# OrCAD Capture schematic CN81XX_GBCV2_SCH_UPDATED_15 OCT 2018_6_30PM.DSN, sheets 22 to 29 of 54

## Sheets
22 23.USB2514BI-USB HUB: size A; title: USB2514BI-USB HUB
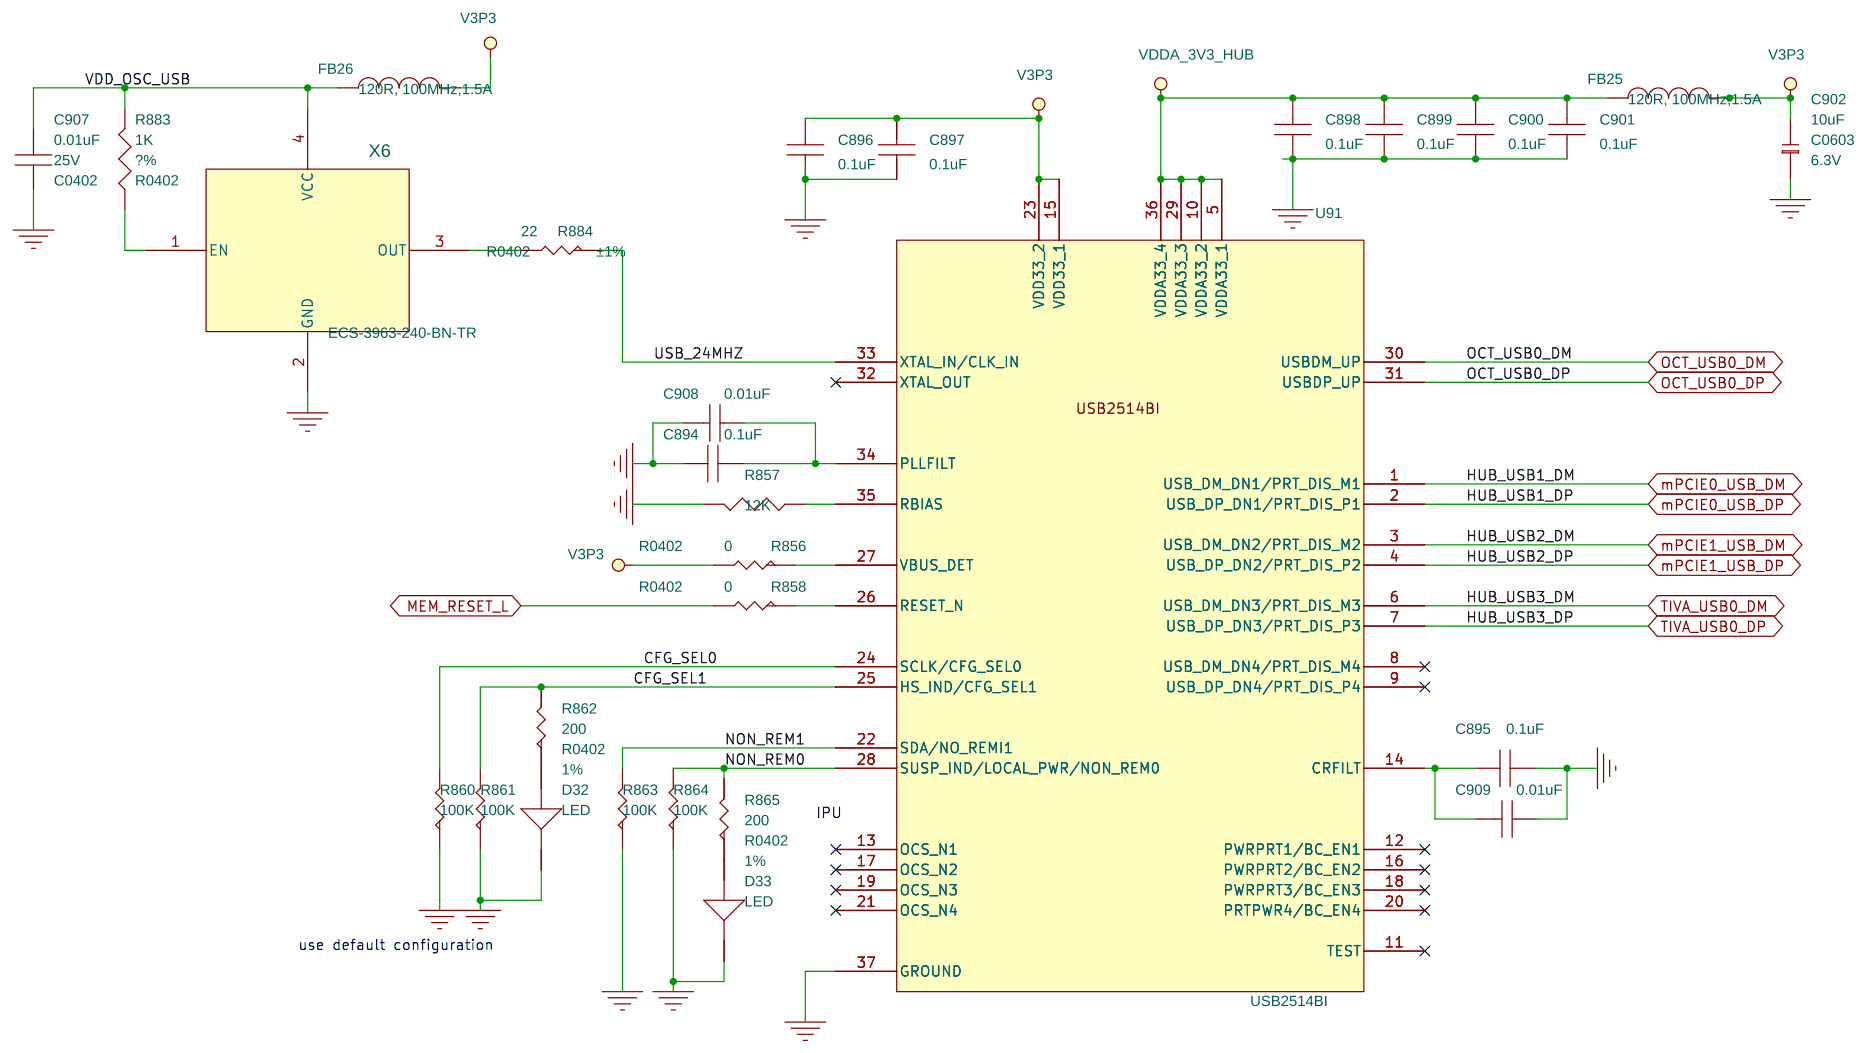
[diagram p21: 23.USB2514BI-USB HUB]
23 24.ETH PORT3 TO BB: size B; title: ETH PORT3 TO BB
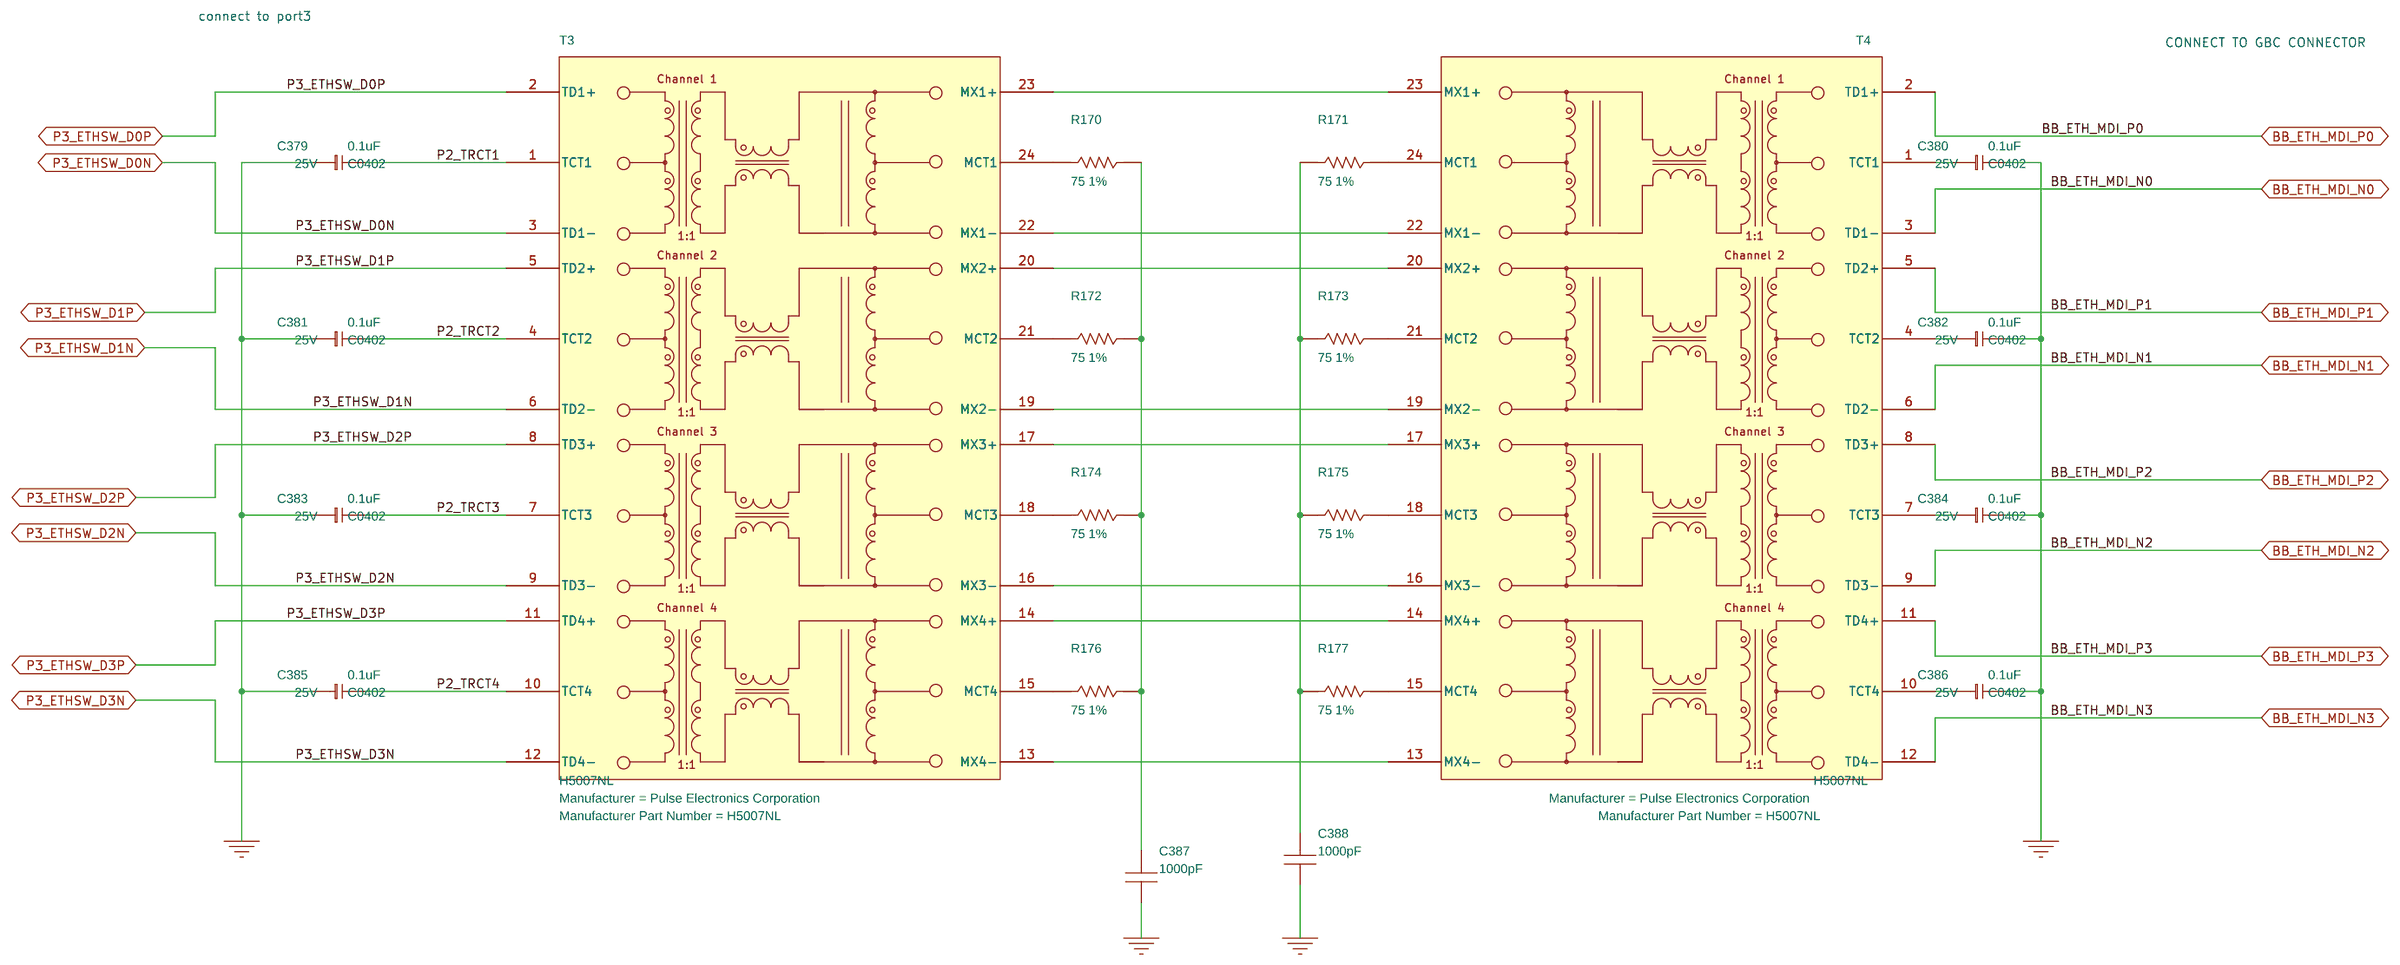
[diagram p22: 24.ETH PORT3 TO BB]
24 26.BOOT SPI FLASH & NAND: size B; title: BOOT SPI FLASH & NAND  FLASH
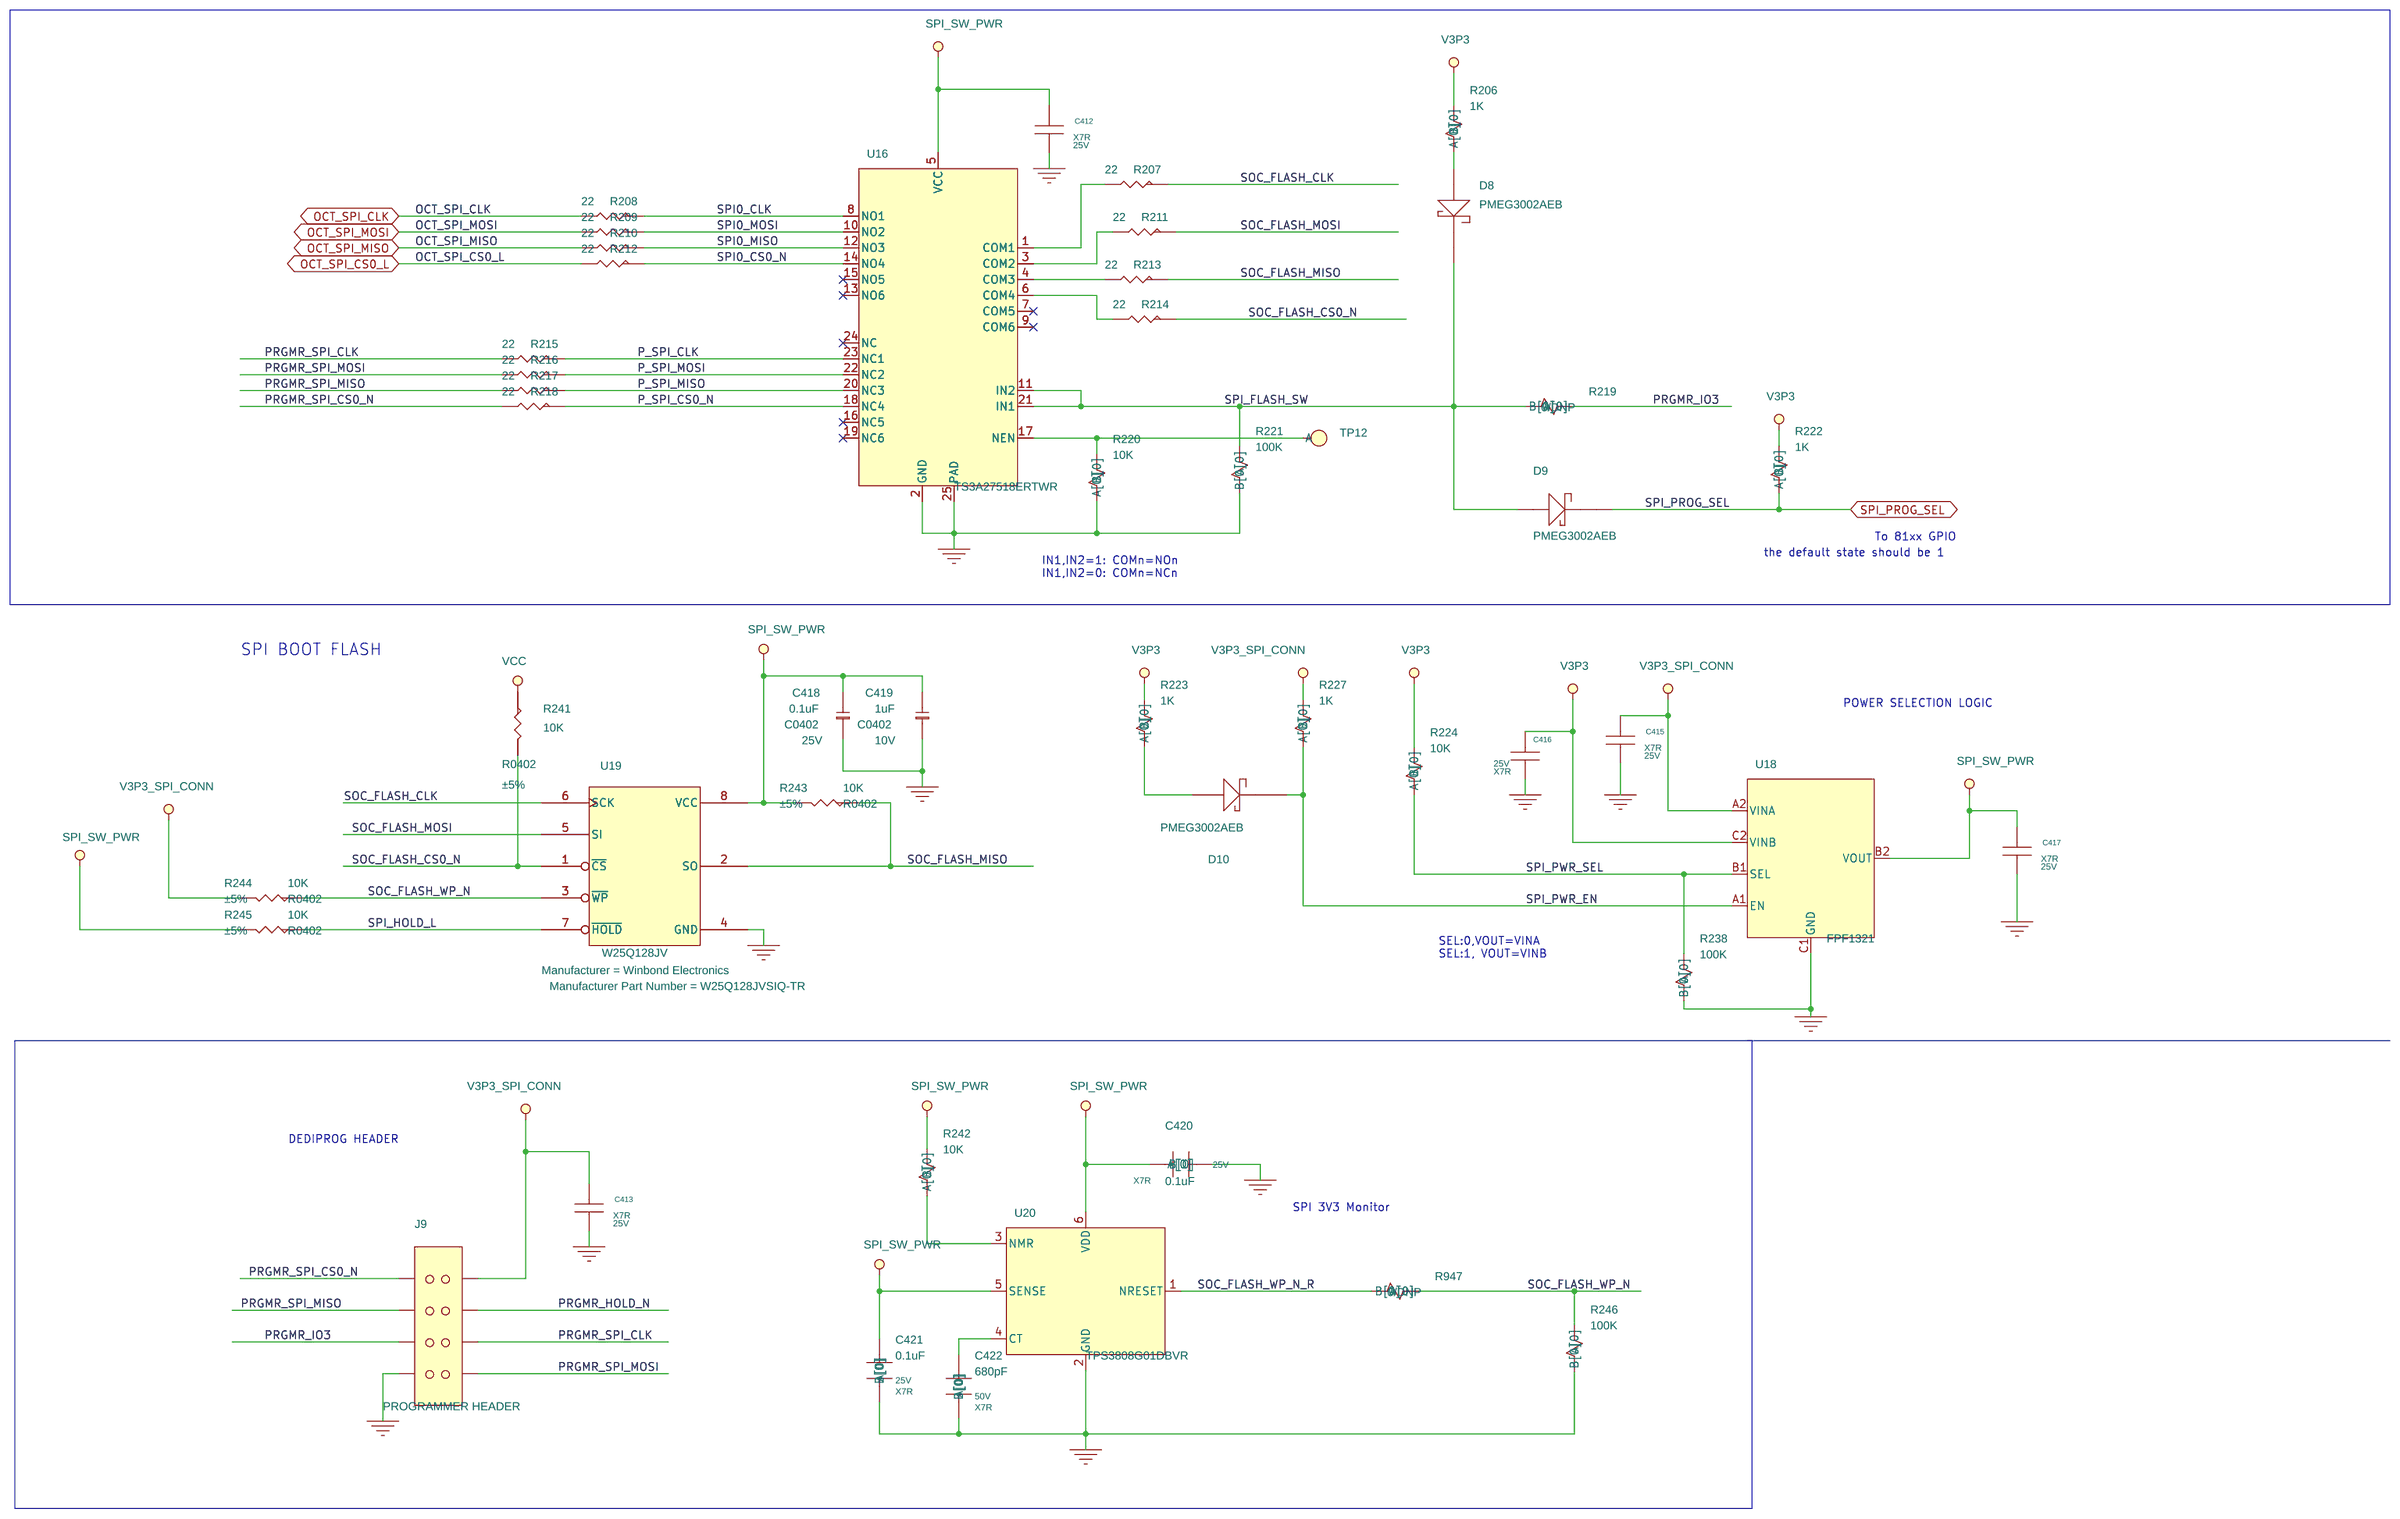
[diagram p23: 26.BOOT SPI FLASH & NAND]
25 27.OCT-UART0: size B; title: OCT-UART 0
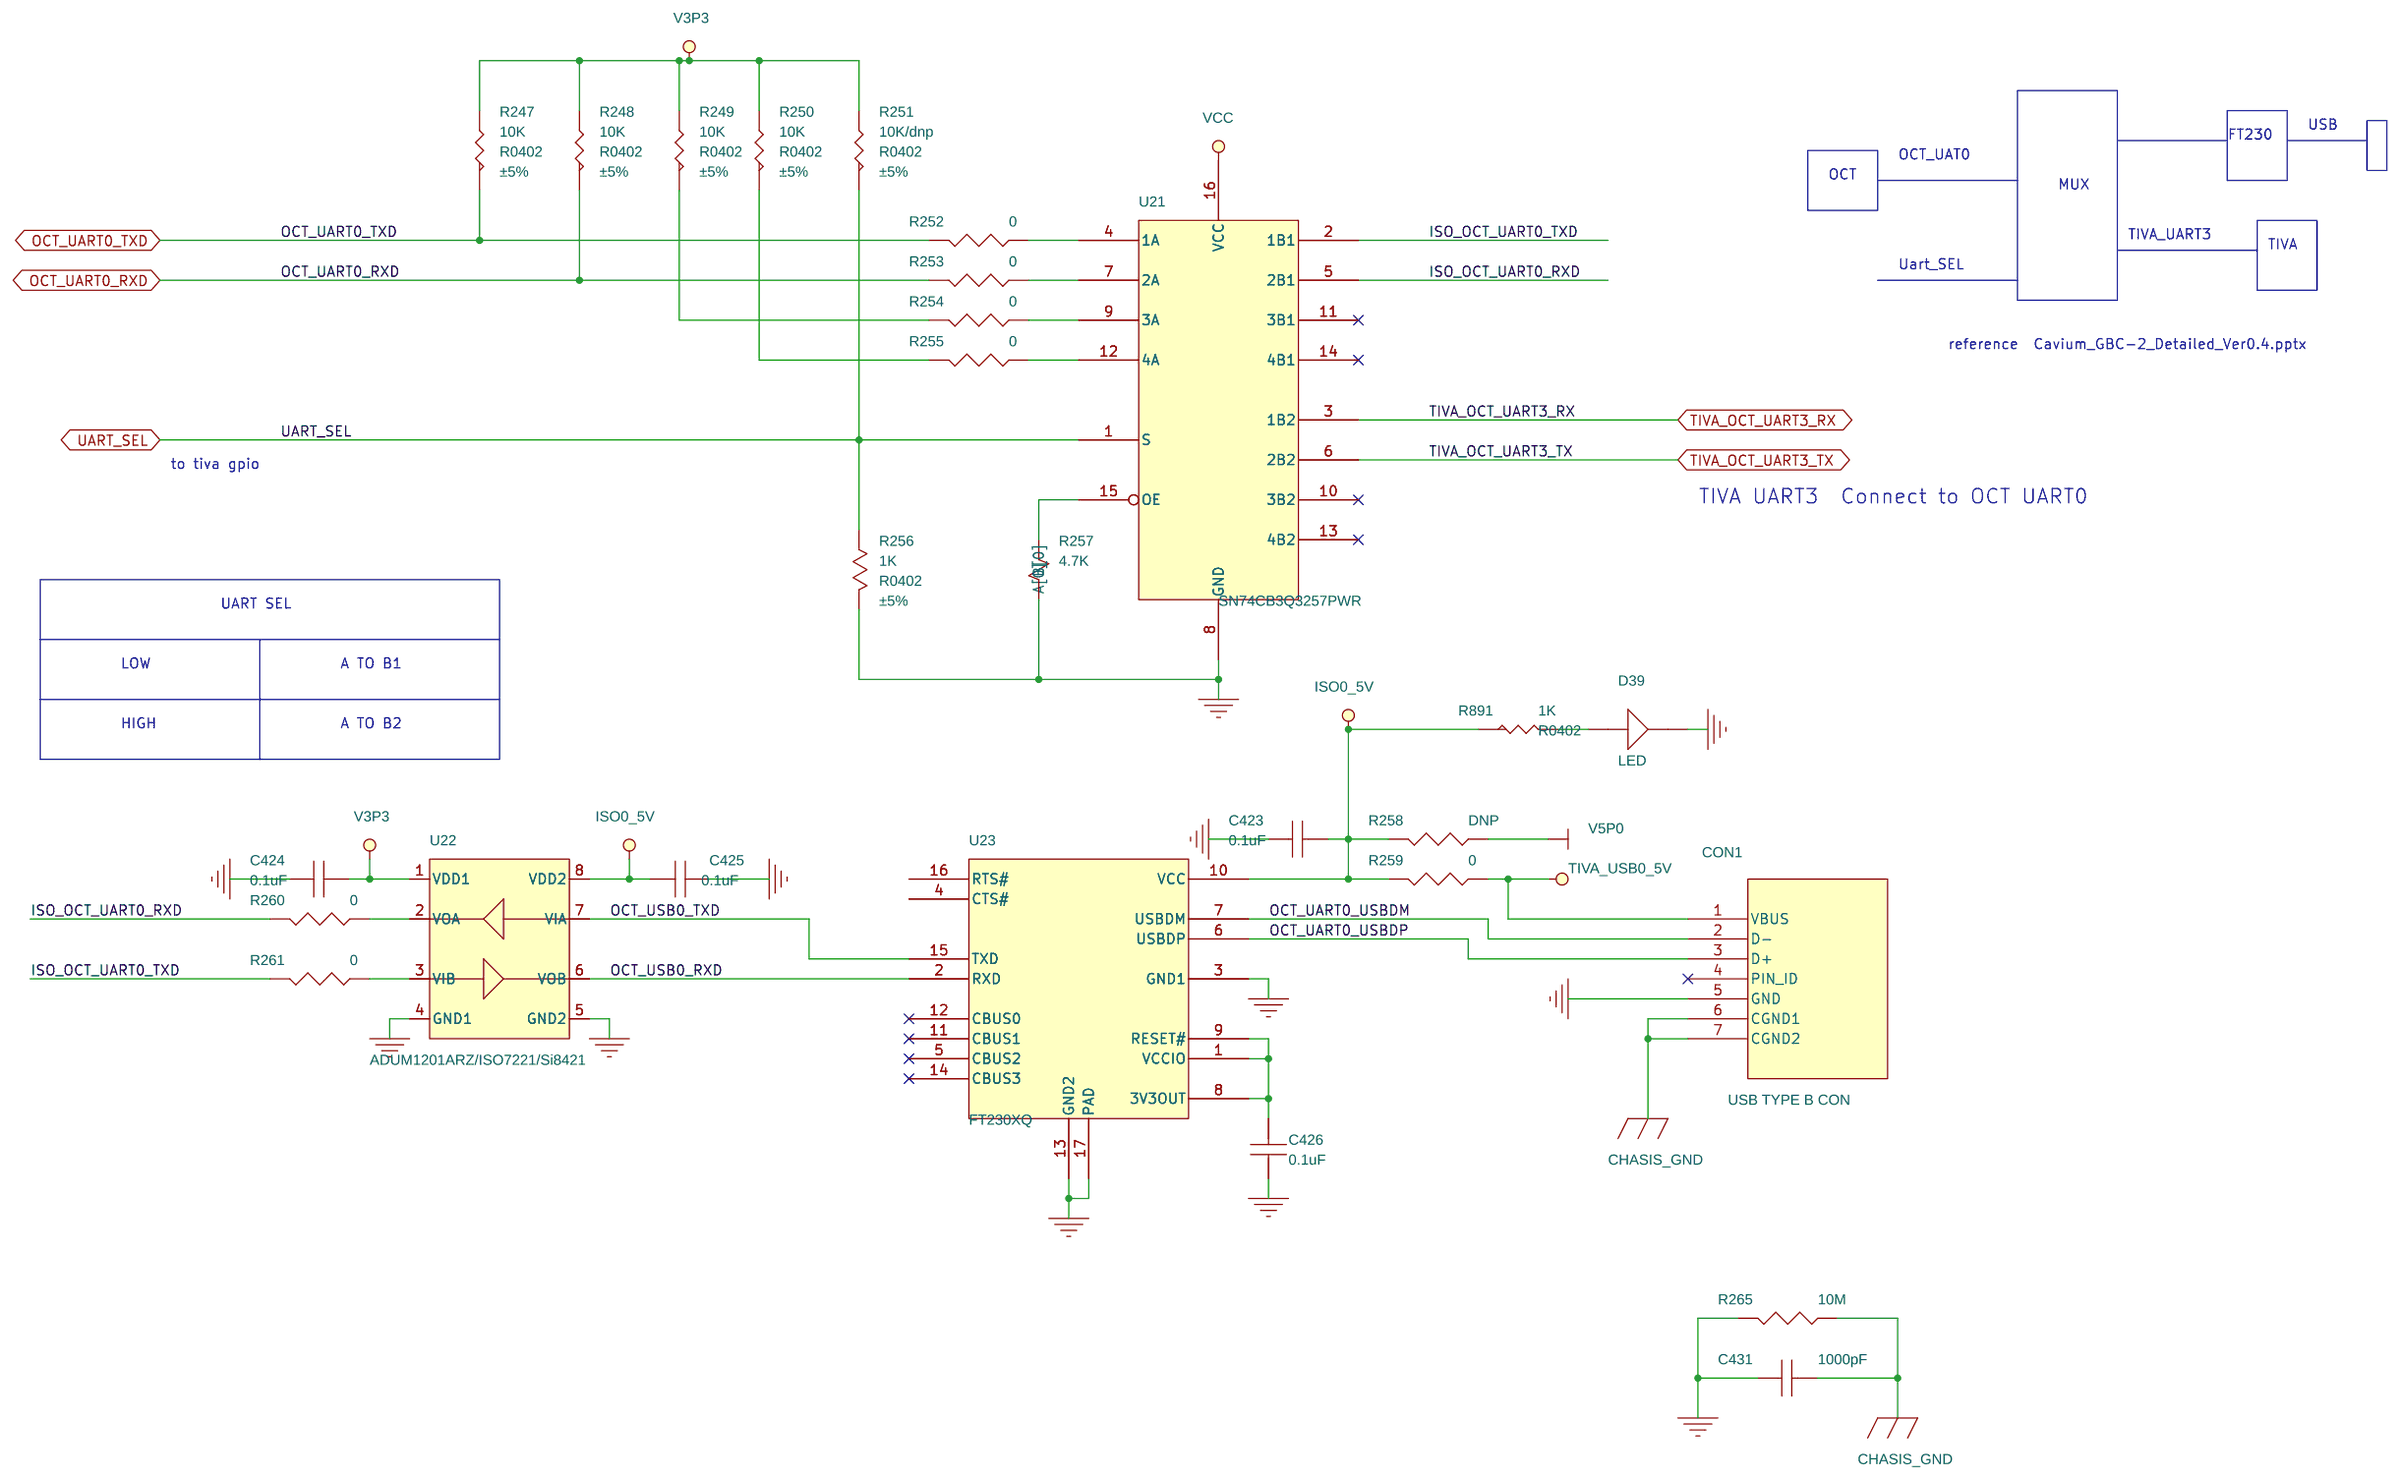
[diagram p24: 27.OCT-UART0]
26 28.DLM2_0 TO MINI PCIE0: size B; title: DLM2_0 TO MINI PCIE
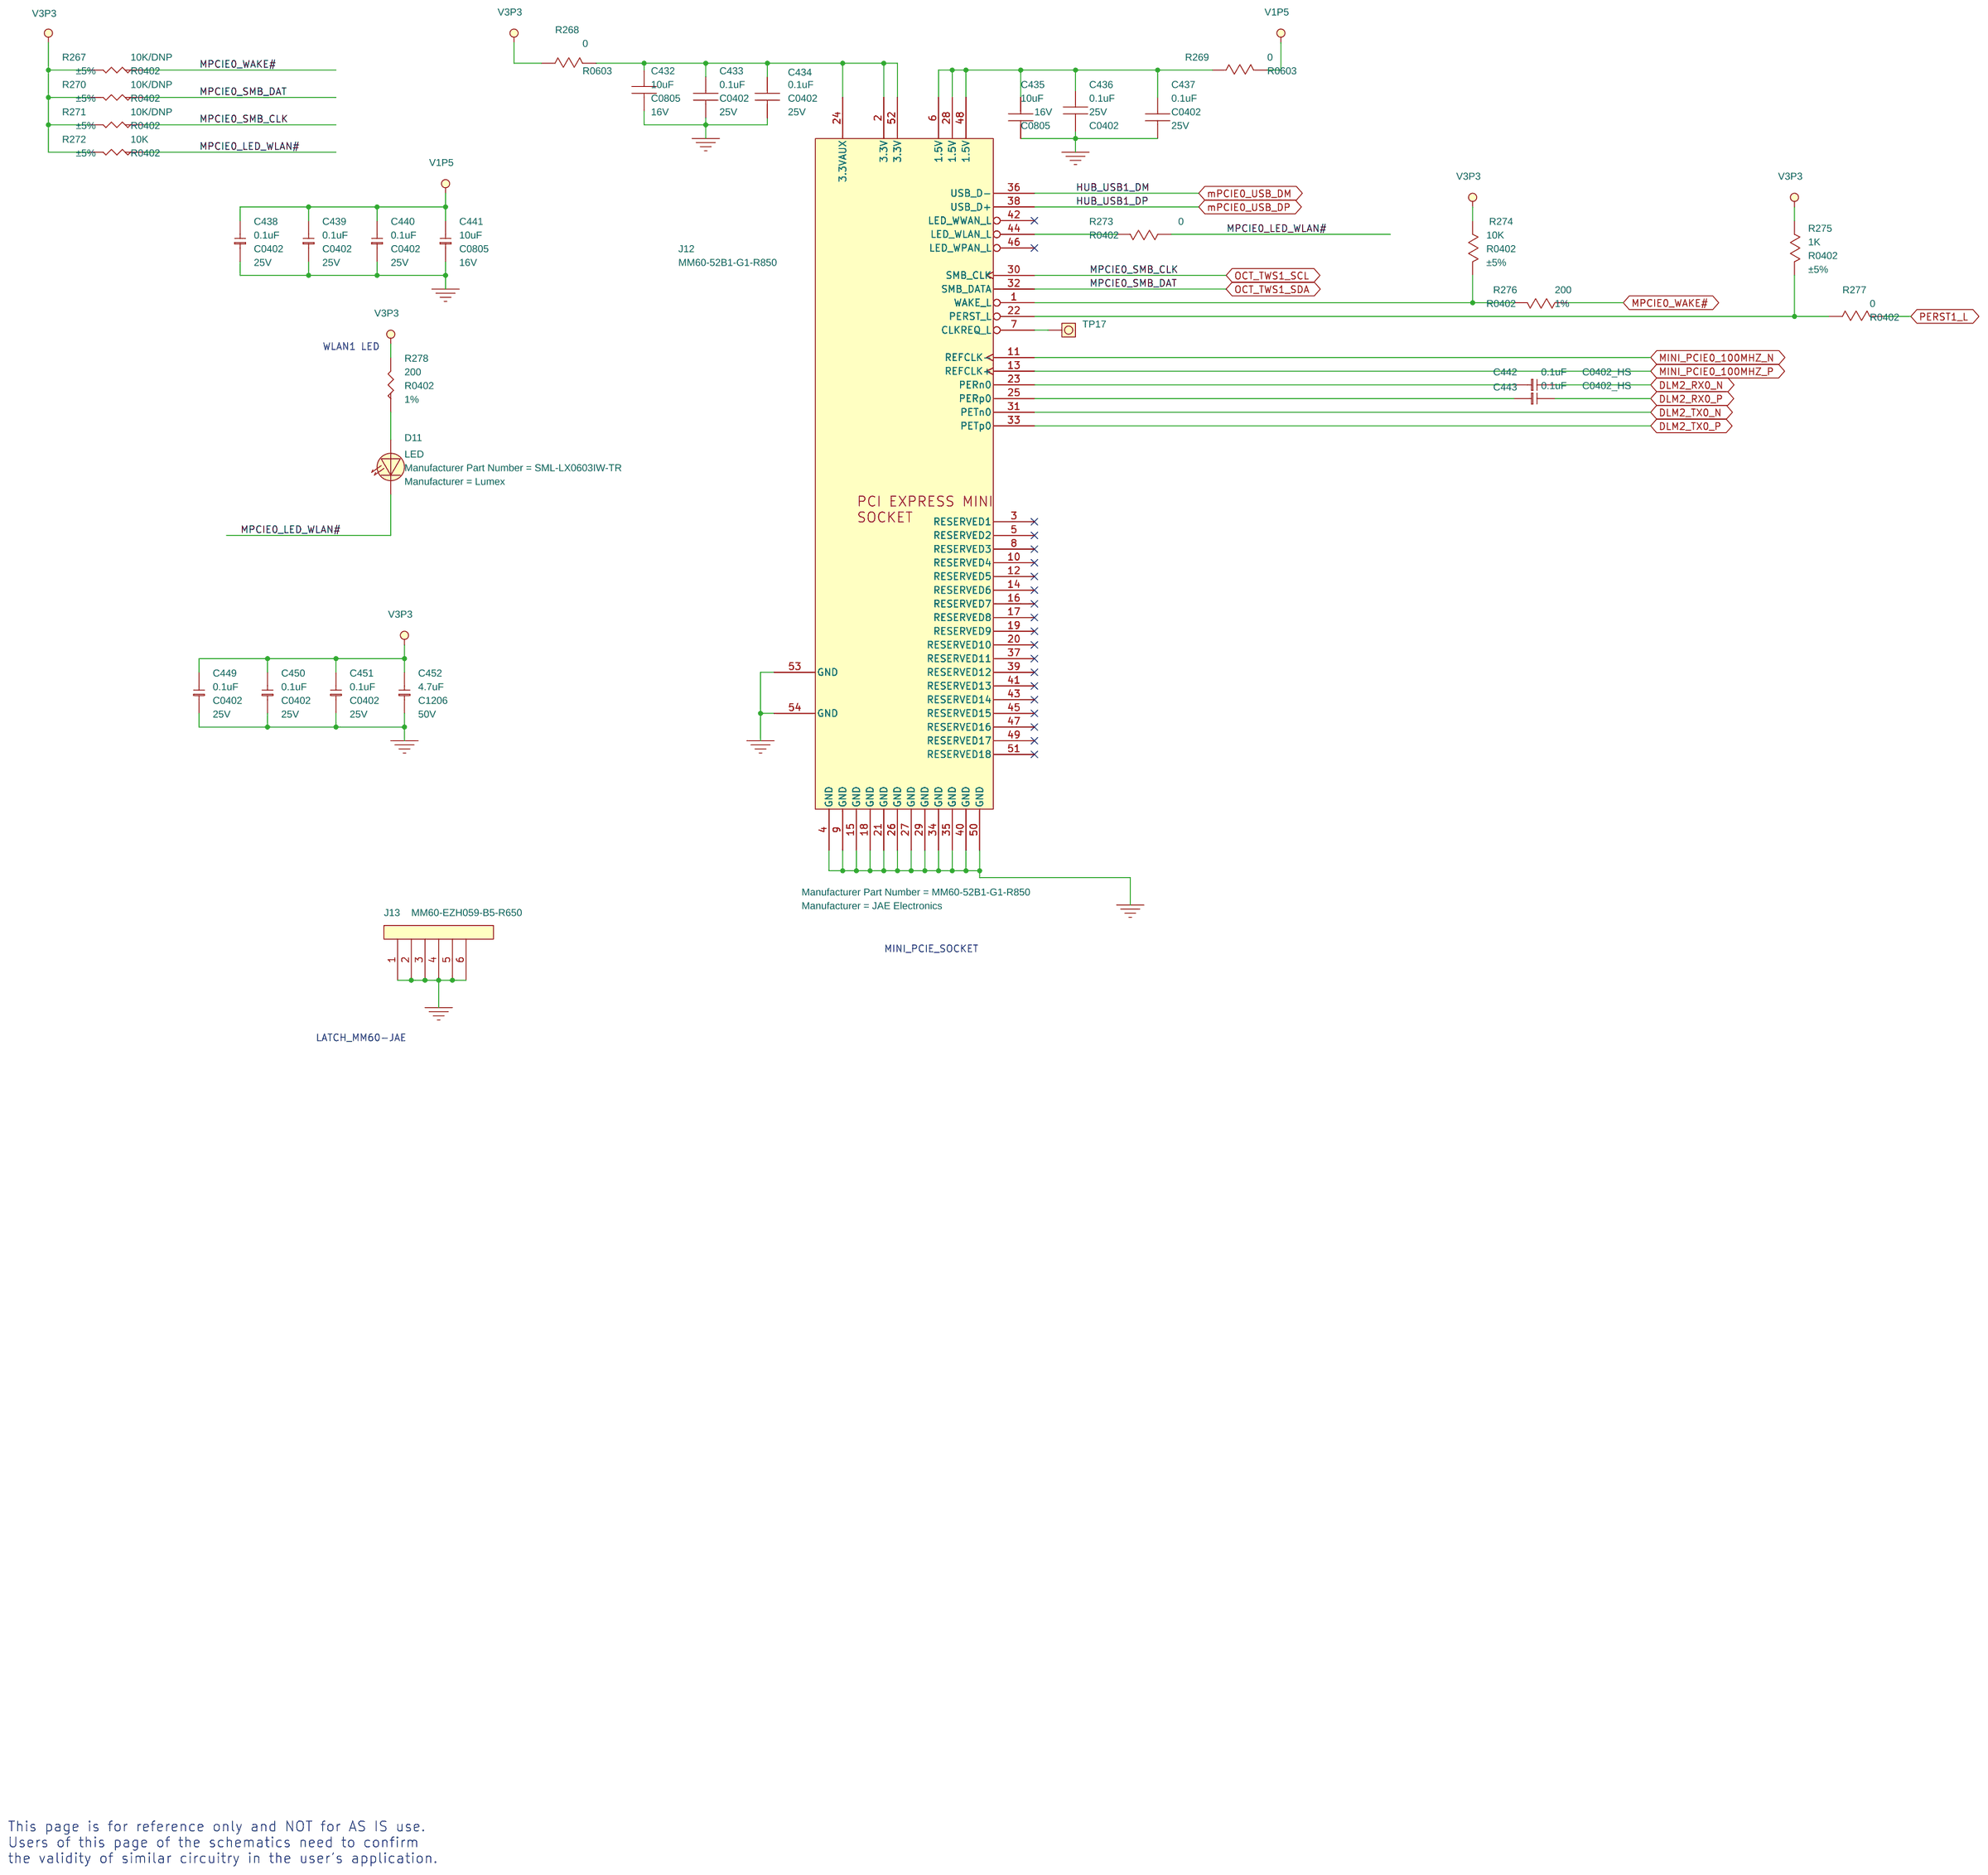
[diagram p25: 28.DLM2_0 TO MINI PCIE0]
27 29.DLM2_1 TO MINI PCIE1: size B; title: DLM2_1 TO MINI PCIE
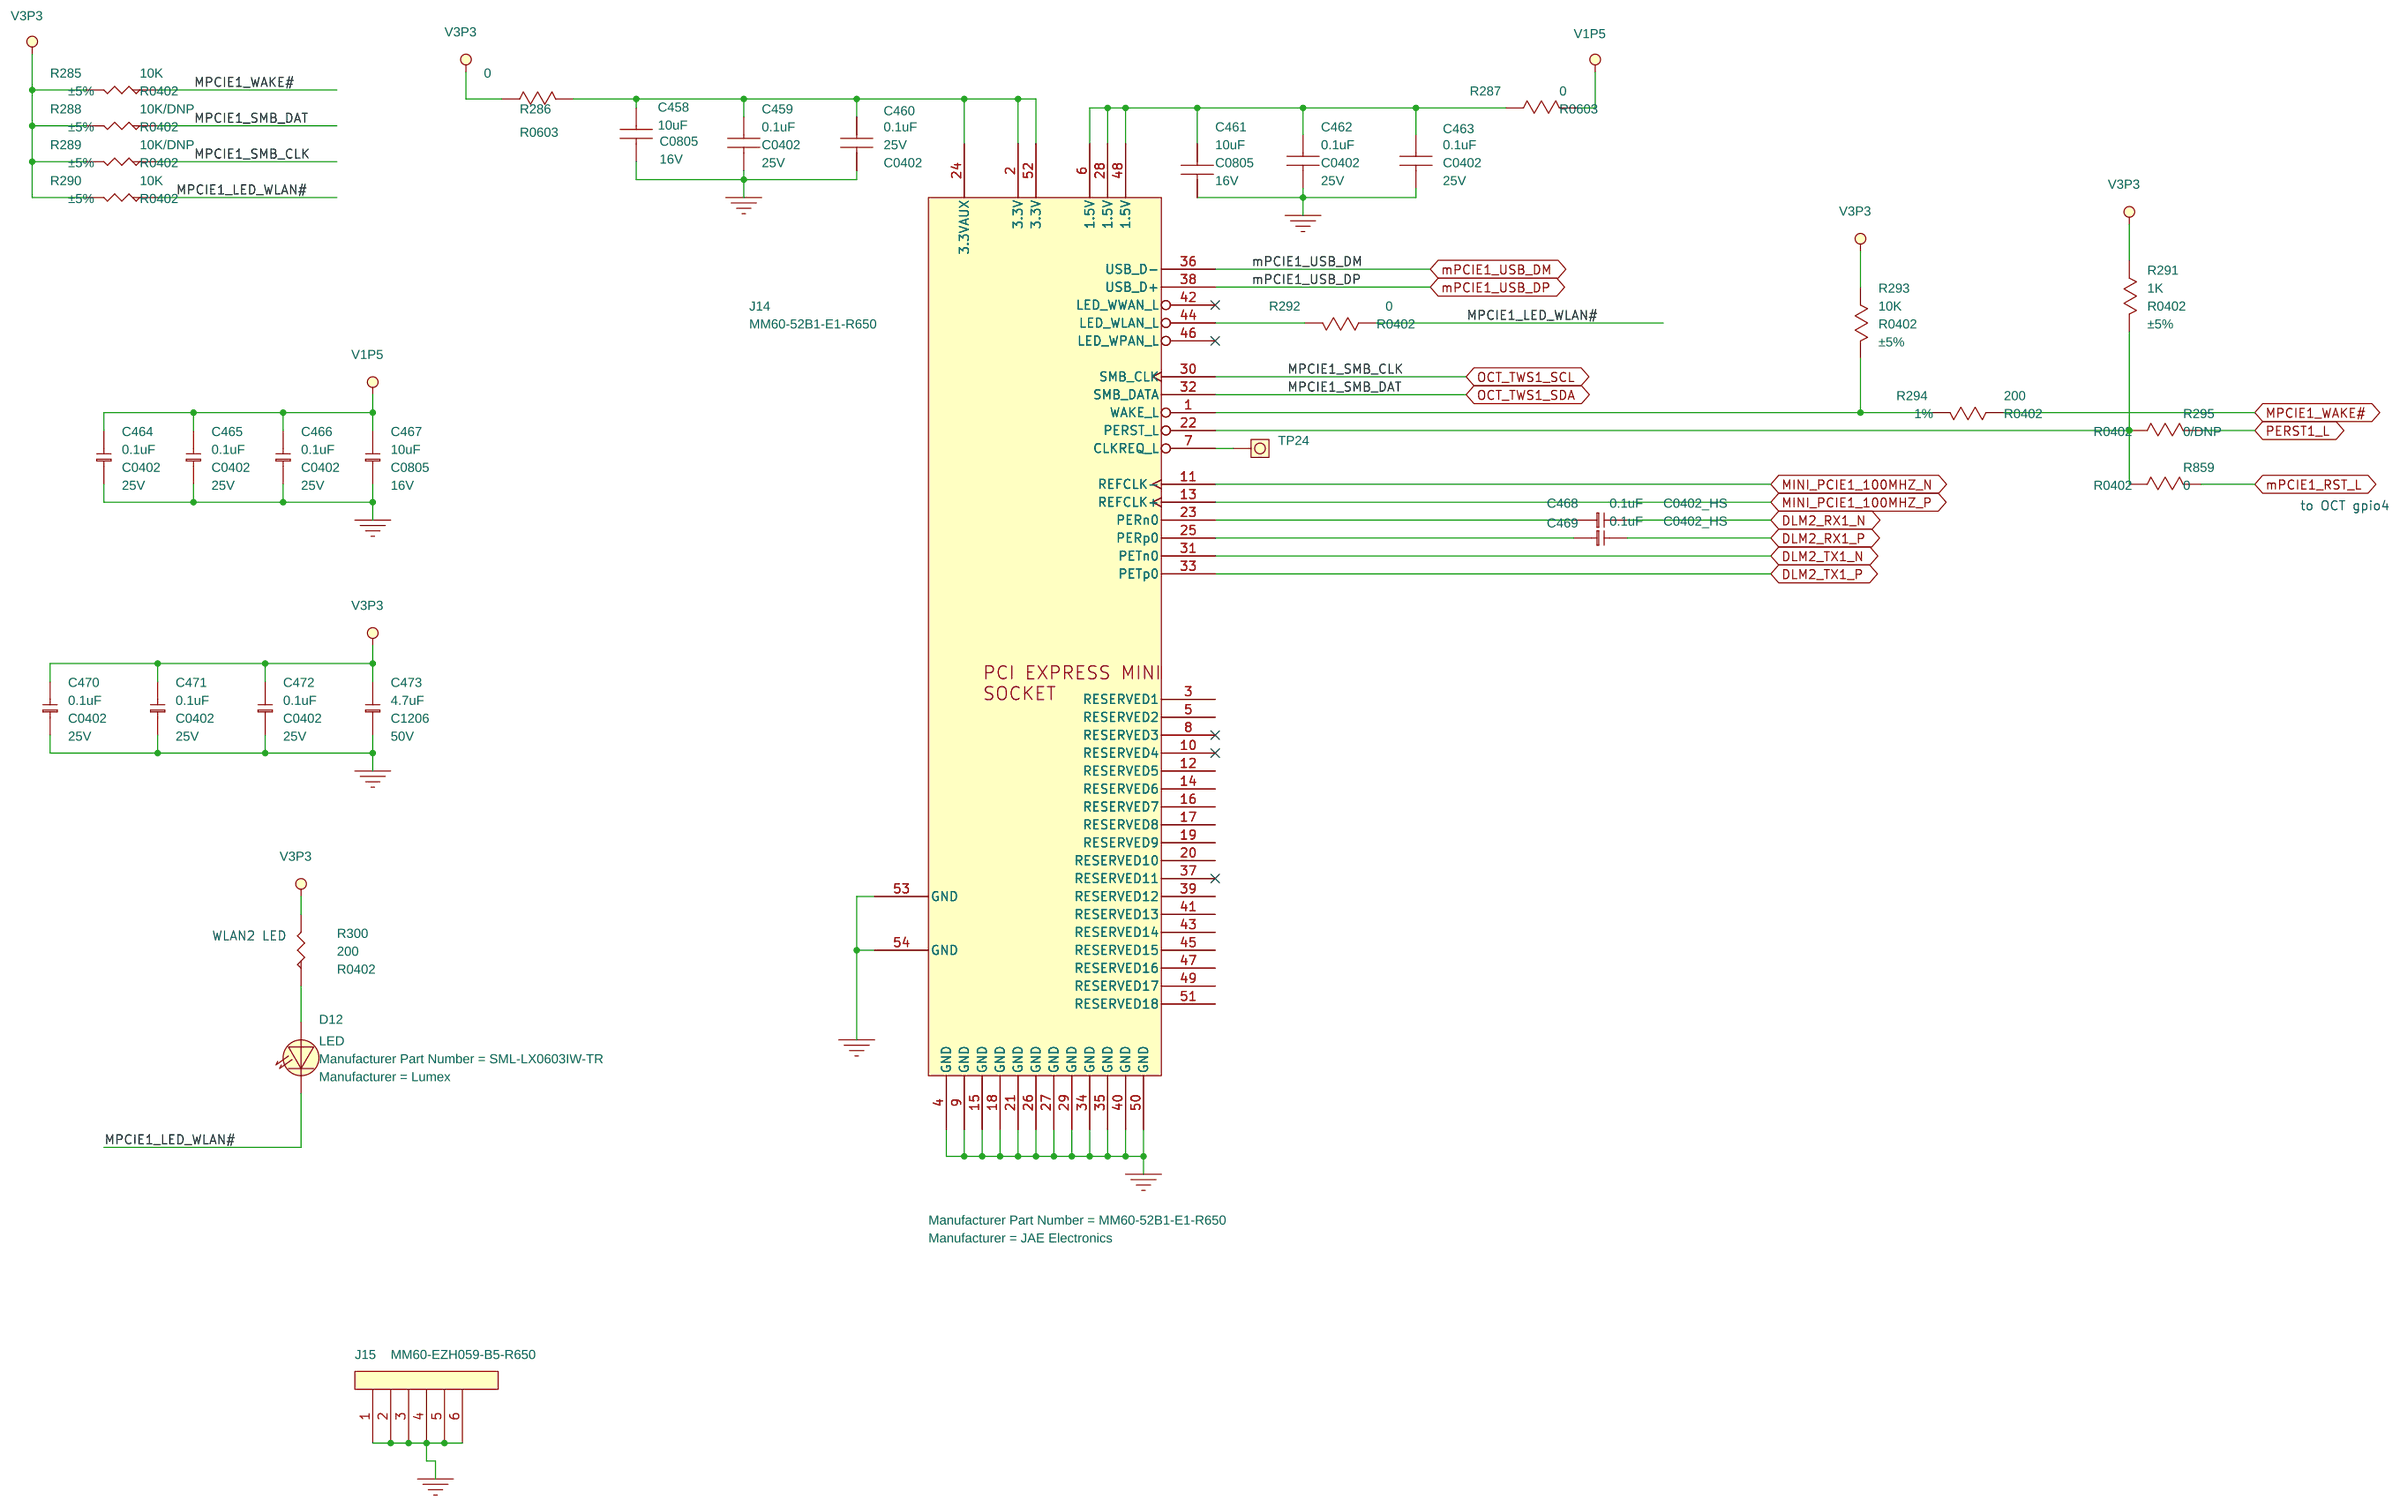
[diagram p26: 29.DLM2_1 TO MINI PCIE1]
28 30.POWER ENTRY: size Custom; title: POWER ENTRY
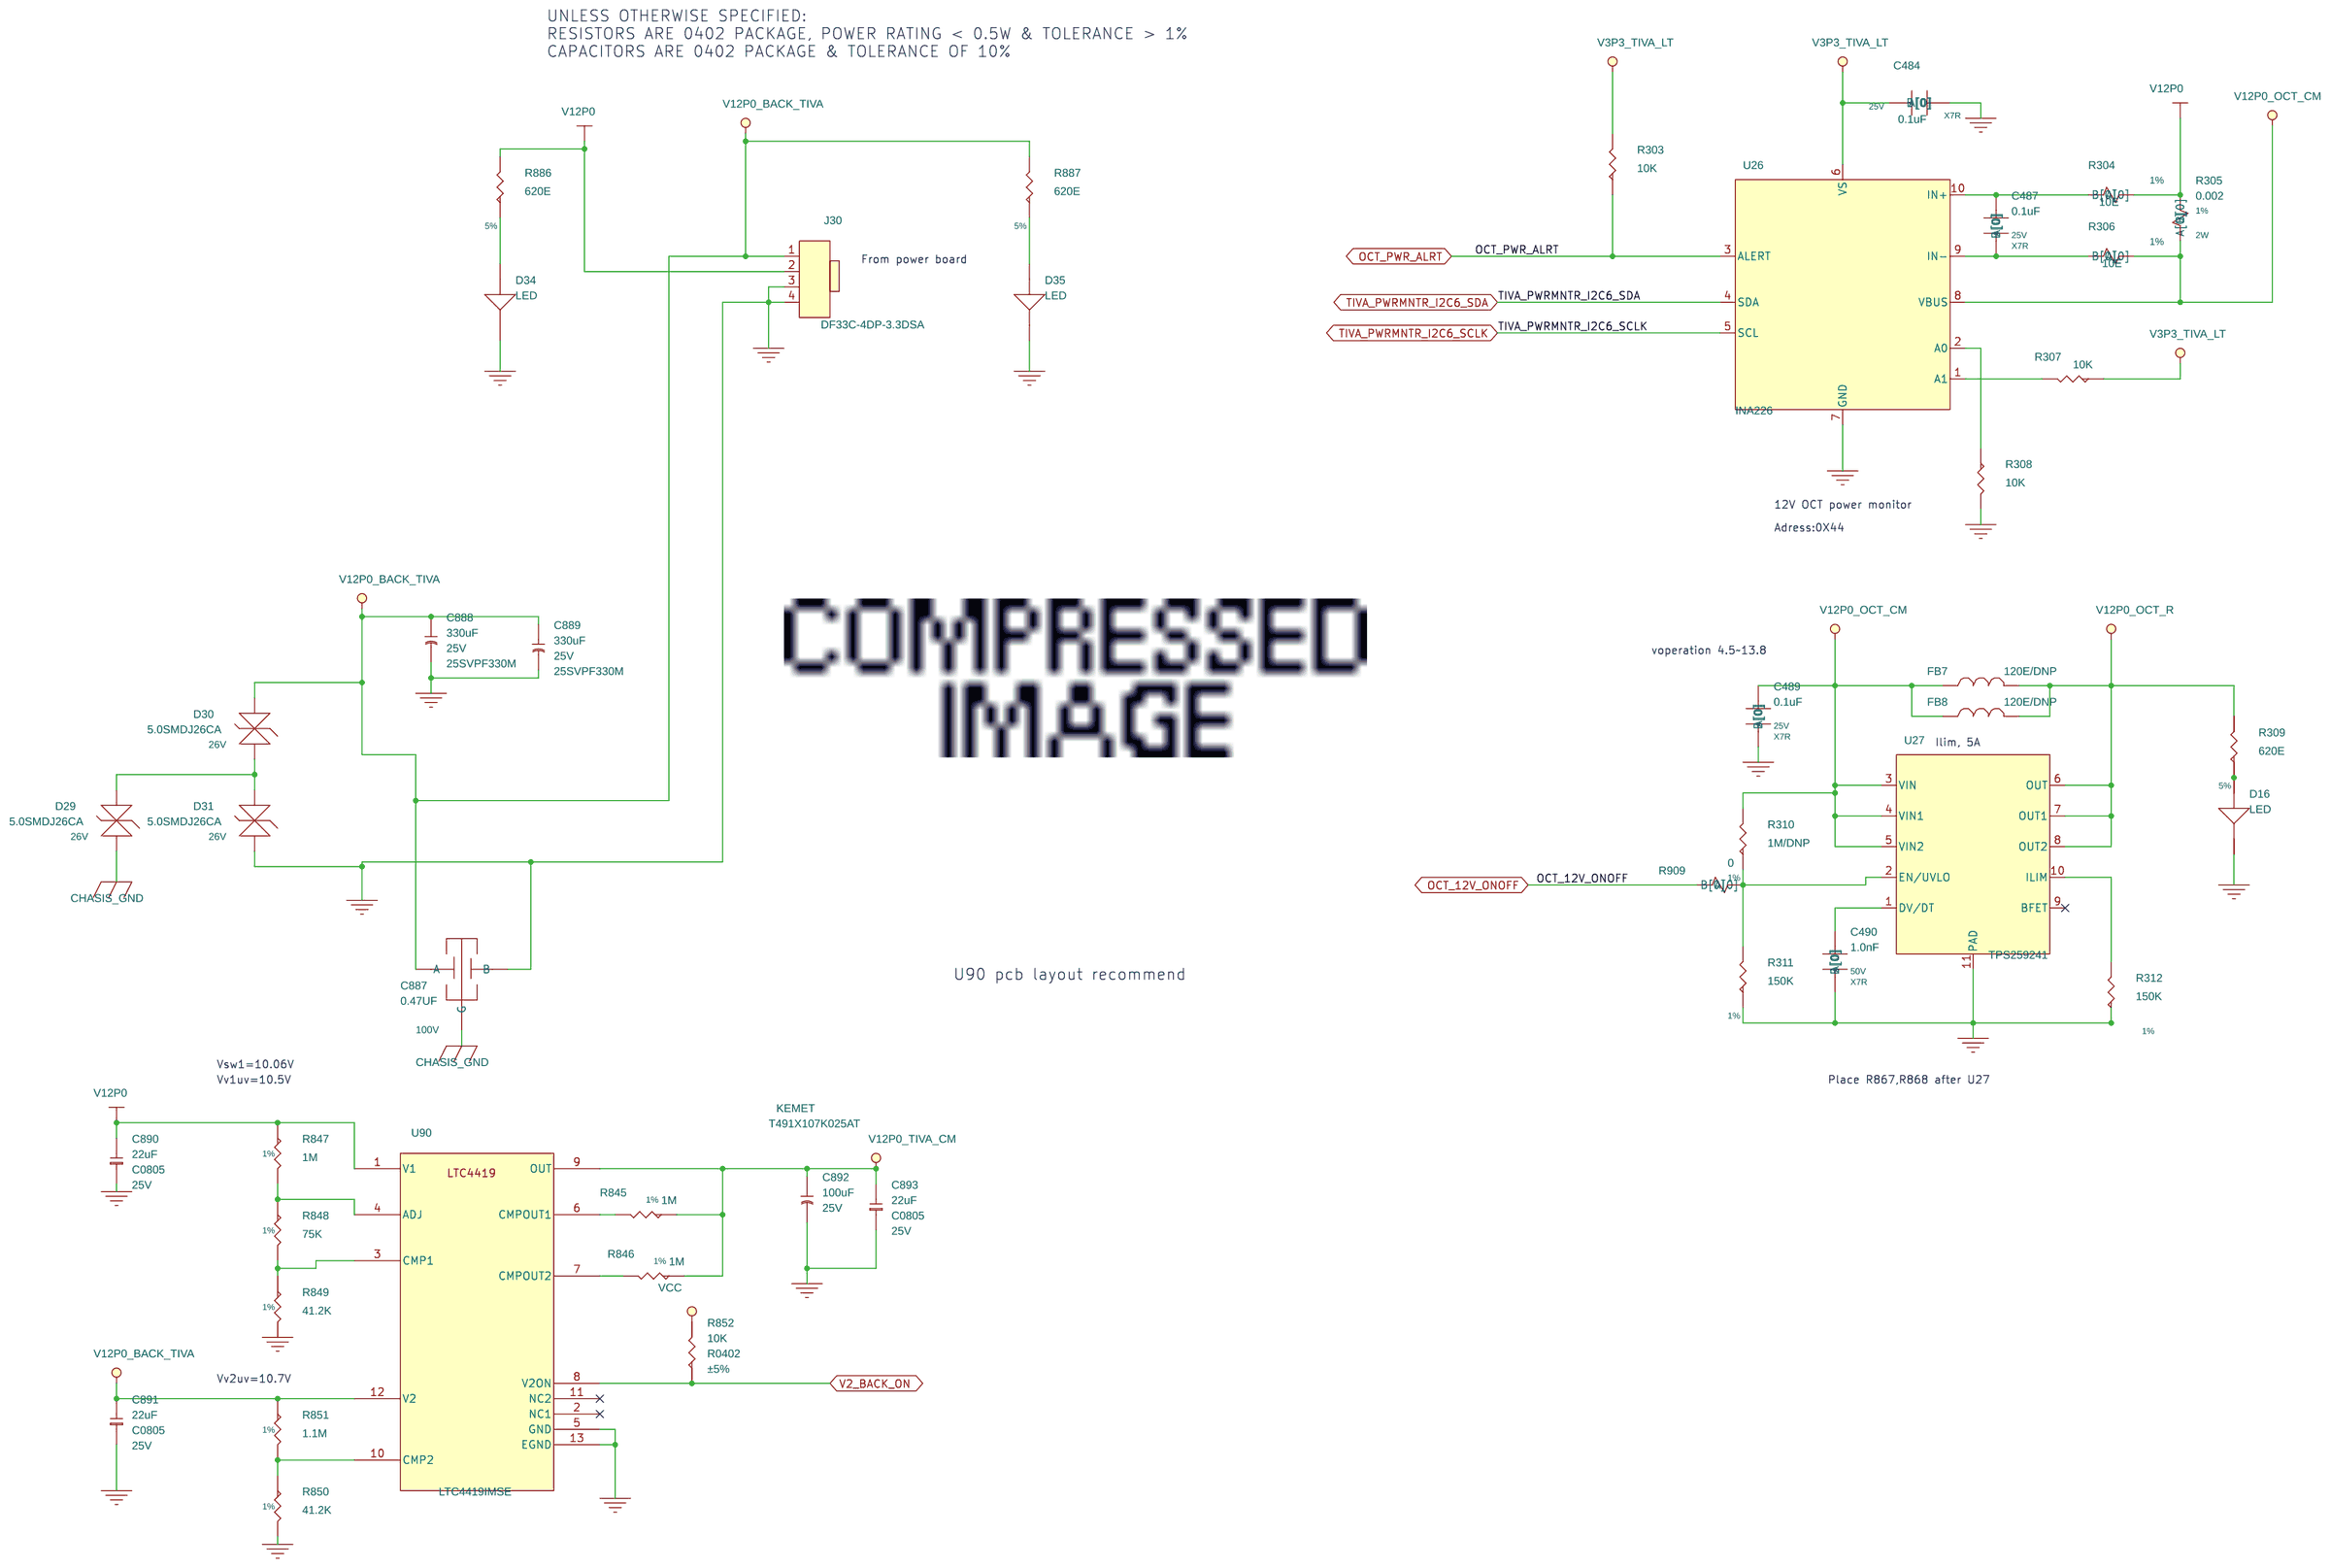
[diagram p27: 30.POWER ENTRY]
29 33.3V3_T & 5V REG: size Custom; title: 3V3_T&5V REG
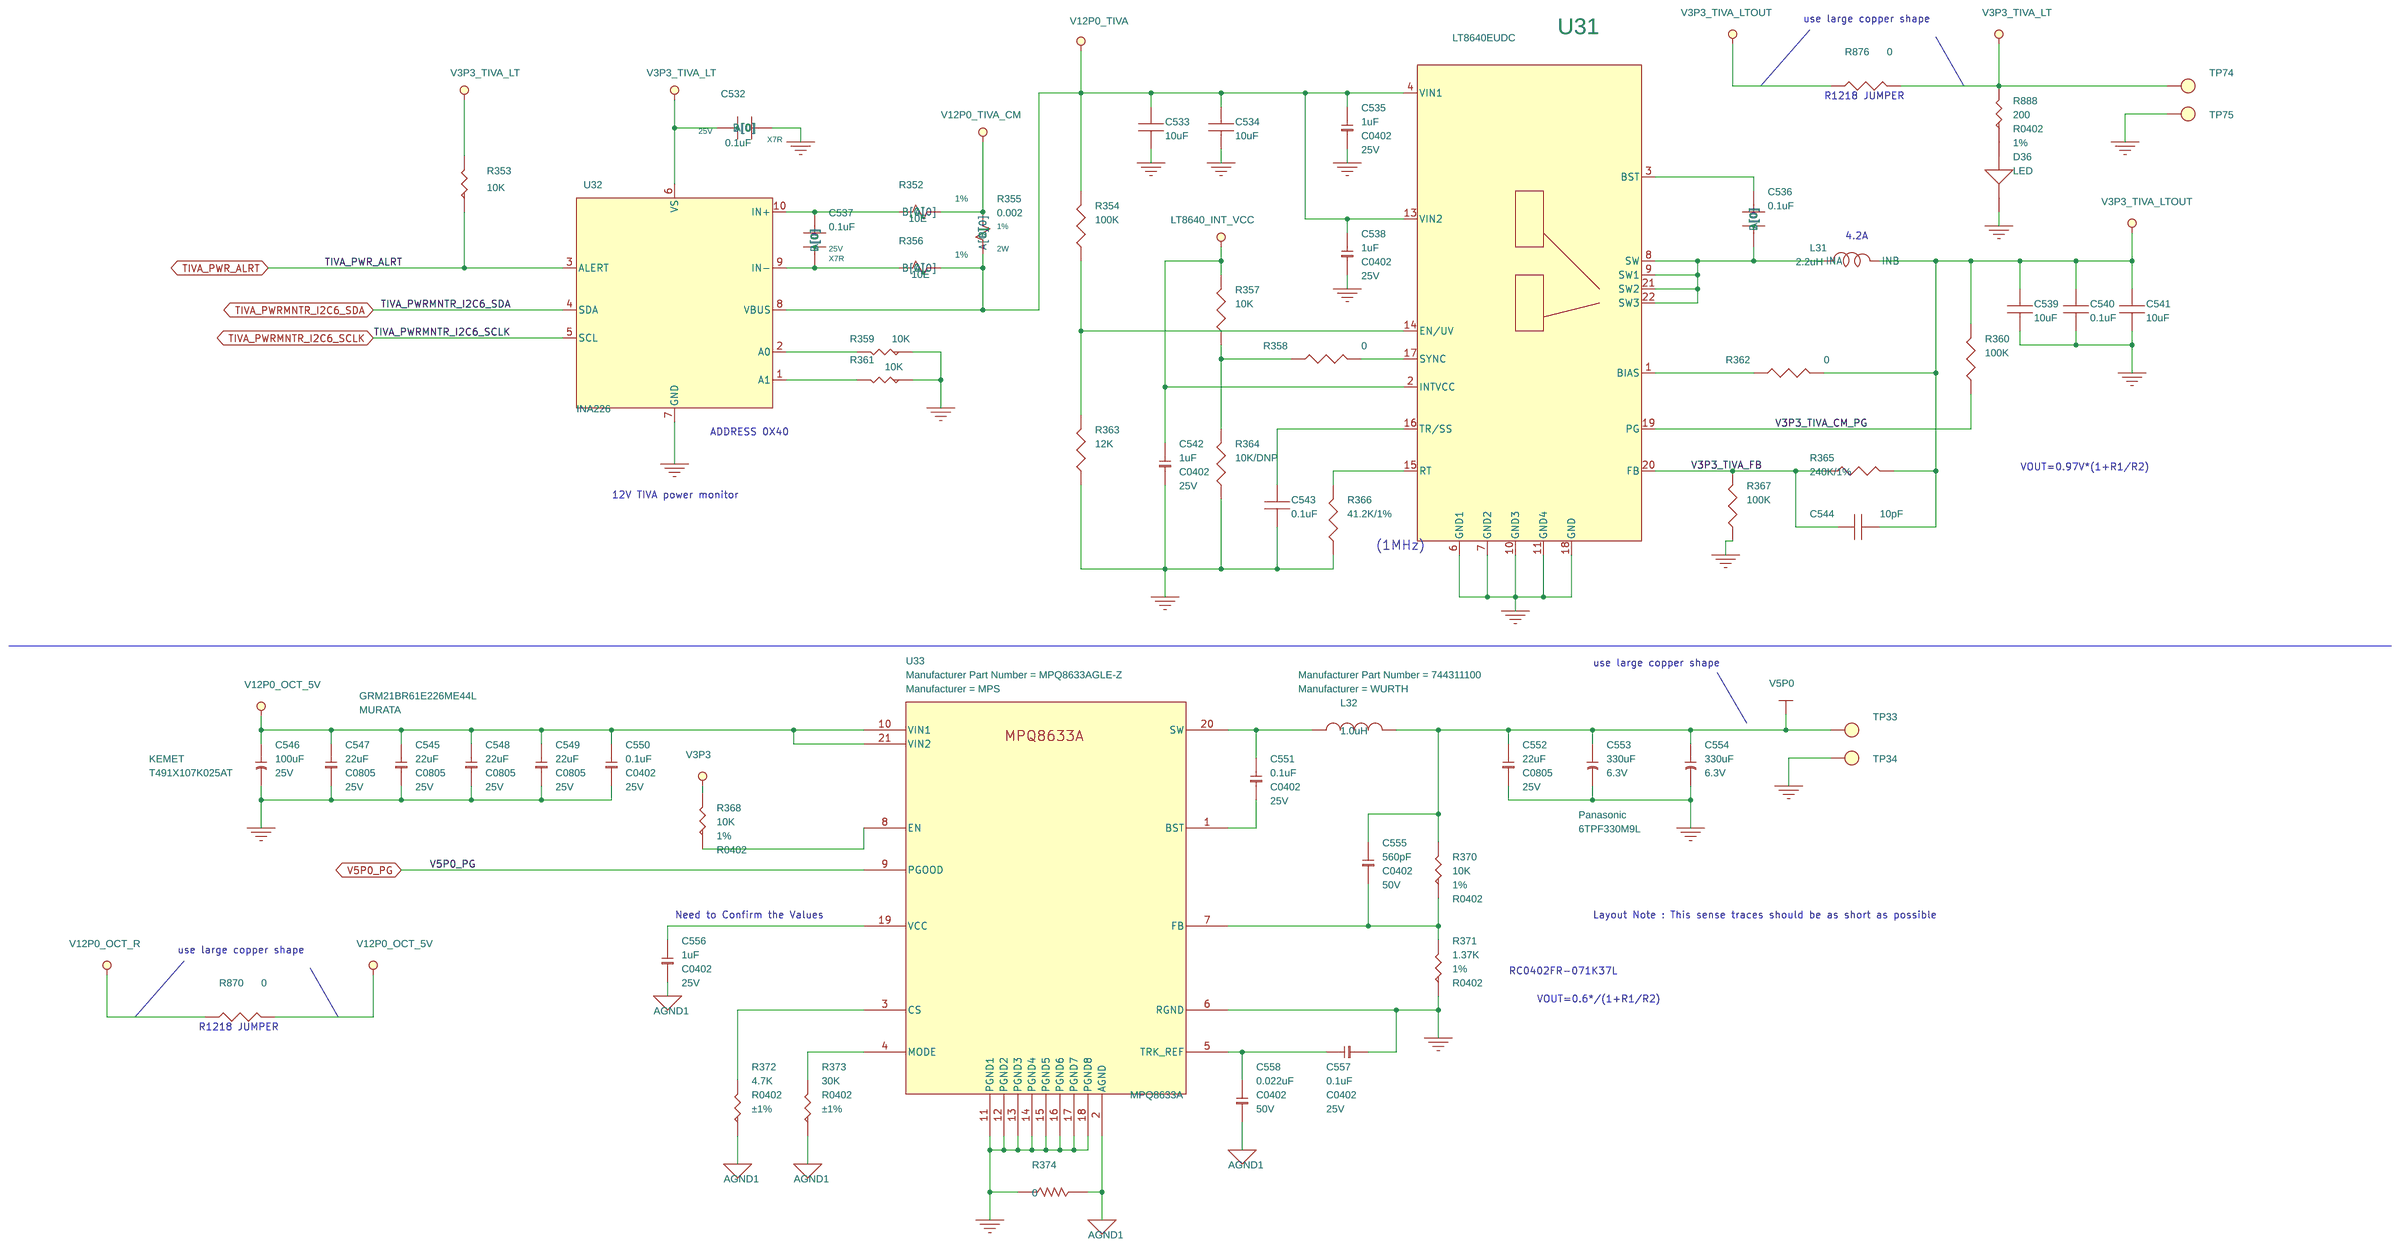
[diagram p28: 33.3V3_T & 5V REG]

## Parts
sheet 23.USB2514BI-USB HUB
C894  0.1uF  [C0402]
C895  0.1uF  [C0402]
C896  0.1uF  [C0402]
C897  0.1uF  [C0402]
C898  0.1uF  [C0402]
C899  0.1uF  [C0402]
C900  0.1uF  [C0402]
C901  0.1uF  [C0402]
C902  10uF  [C0603]
C907  0.01uF  [C0402]
C908  0.01uF  [C0402]
C909  0.01uF  [C0402]
D32  LED  [LED_LTST-C190]
D33  LED  [LED_LTST-C190]
FB25  120R, 100MHz,1.5A  [L0402]
FB26  120R, 100MHz,1.5A  [L0402]
R856  0  [R0402]
R857  12K  [R0402]
R858  0  [R0402]
R860  100K  [R0402]
R861  100K  [R0402]
R862  200  [R0402]
R863  100K  [R0402]
R864  100K  [R0402]
R865  200  [R0402]
R883  1K  [R0402]
R884  22  [R0402]
U91  USB2514BI  [SQFN36-050-0606LH]
X6  ECS-3963-240-BN-TR  [4smd-5x3_2x1_3mm]
sheet 24.ETH PORT3 TO BB
C379  0.1uF  [C0402]
C380  0.1uF  [C0402]
C381  0.1uF  [C0402]
C382  0.1uF  [C0402]
C383  0.1uF  [C0402]
C384  0.1uF  [C0402]
C385  0.1uF  [C0402]
C386  0.1uF  [C0402]
C387  1000pF  [C1812]
C388  1000pF  [C1812]
R170  75  [R0603]
R171  75  [R0603]
R172  75  [R0603]
R173  75  [R0603]
R174  75  [R0603]
R175  75  [R0603]
R176  75  [R0603]
R177  75  [R0603]
T3  H5007NL  [H5007NL]
T4  H5007NL  [H5007NL]
sheet 26.BOOT SPI FLASH & NAND
C412  0.1uF  [C0402]
C413  0.1uF  [C0402]
C415  0.1uF  [C0402]
C416  0.1uF  [C0402]
C417  0.1uF  [C0402]
C418  0.1uF  [C0402]
C419  1uF  [C0402]
C420  0.1uF  [C0402]
C421  0.1uF  [C0402]
C422  680pF  [C0402]
D8  PMEG3002AEB  [SODFL1608X65N_AEE]
D9  PMEG3002AEB  [SODFL1608X65N_AEE]
D10  PMEG3002AEB  [SODFL1608X65N_AEE]
J9  PROGRAMMER HEADER  [20021121-00008C4LF]
R206  1K  [R0402]
R207  22  [R0402]
R208  22  [R0402]
R209  22  [R0402]
R210  22  [R0402]
R211  22  [R0402]
R212  22  [R0402]
R213  22  [R0402]
R214  22  [R0402]
R215  22  [R0402]
R216  22  [R0402]
R217  22  [R0402]
R218  22  [R0402]
R219  0/DNP  [R0402]
R220  10K  [R0402]
R221  100K  [R0402]
R222  1K  [R0402]
R223  1K  [R0402]
R224  10K  [R0402]
R227  1K  [R0402]
R238  100K  [R0402]
R241  10K  [R0402]
R242  10K  [R0402]
R243  10K  [R0402]
R244  10K  [R0402]
R245  10K  [R0402]
R246  100K  [R0402]
R947  0/DNP  [R0402]
TP12  ?  [TP_50]
U16  TS3A27518ERTWR  [TS3A27518ERTWR]
U18  FPF1321  [FPF1320UCX]
U19  W25Q128JV  [8SOIC_N25Q128A]
U20  TPS3808G01DBVR  [SOT95P280X145-6N]
sheet 27.OCT-UART0
C423  0.1uF  [C0402]
C424  0.1uF  [C0402]
C425  0.1uF  [C0402]
C426  0.1uF  [C0402]
C431  1000pF  [C1812]
CON1  USB TYPE B CON  [UE25BE5510H]
D39  LED  [LED_LTST-C190]
R247  10K  [R0402]
R248  10K  [R0402]
R249  10K  [R0402]
R250  10K  [R0402]
R251  10K/dnp  [R0402]
R252  0  [R0402]
R253  0  [R0402]
R254  0  [R0402]
R255  0  [R0402]
R256  1K  [R0402]
R257  4.7K  [R0402]
R258  DNP  [R0402]
R259  0  [R0402]
R260  0  [R0402]
R261  0  [R0402]
R265  10M  [R0402]
R891  1K  [R0402]
U21  SN74CB3Q3257PWR  [TSSOP65P640X120-16N]
U22  ADUM1201ARZ/ISO7221/Si8421  [SO8]
U23  FT230XQ  [QFN_16]
sheet 28.DLM2_0 TO MINI PCIE0
C432  10uF  [C0805]
C433  0.1uF  [C0402]
C434  0.1uF  [C0402]
C435  10uF  [C0805]
C436  0.1uF  [C0402]
C437  0.1uF  [C0402]
C438  0.1uF  [C0402]
C439  0.1uF  [C0402]
C440  0.1uF  [C0402]
C441  10uF  [C0805]
C442  0.1uF  [C0402_HS]
C443  0.1uF  [C0402_HS]
C449  0.1uF  [C0402]
C450  0.1uF  [C0402]
C451  0.1uF  [C0402]
C452  4.7uF  [C1206]
D11  LED  [D0603]
J12  MM60-52B1-G1-R850  [MM60_52B1_G1_R850]
J13  MM60-EZH059-B5-R650  [latch_mm60-jae]
R267  10K/DNP  [R0402]
R268  0  [R0603]
R269  0  [R0603]
R270  10K/DNP  [R0402]
R271  10K/DNP  [R0402]
R272  10K  [R0402]
R273  0  [R0402]
R274  10K  [R0402]
R275  1K  [R0402]
R276  200  [R0402]
R277  0  [R0402]
R278  200  [R0402]
TP17  @TEST POINT  [TP_SMD]
sheet 29.DLM2_1 TO MINI PCIE1
C458  10uF  [C0805]
C459  0.1uF  [C0402]
C460  0.1uF  [C0402]
C461  10uF  [C0805]
C462  0.1uF  [C0402]
C463  0.1uF  [C0402]
C464  0.1uF  [C0402]
C465  0.1uF  [C0402]
C466  0.1uF  [C0402]
C467  10uF  [C0805]
C468  0.1uF  [C0402_HS]
C469  0.1uF  [C0402_HS]
C470  0.1uF  [C0402]
C471  0.1uF  [C0402]
C472  0.1uF  [C0402]
C473  4.7uF  [C1206]
D12  LED  [D0603]
J14  MM60-52B1-E1-R650  [MM60_52B1_G1_R850]
J15  MM60-EZH059-B5-R650  [latch_mm60-jae]
R285  10K  [R0402]
R286  0  [R0603]
R287  0  [R0603]
R288  10K/DNP  [R0402]
R289  10K/DNP  [R0402]
R290  10K  [R0402]
R291  1K  [R0402]
R292  0  [R0402]
R293  10K  [R0402]
R294  200  [R0402]
R295  0/DNP  [R0402]
R300  200  [R0402]
R859  0  [R0402]
TP24  @TEST POINT  [TP_SMD]
sheet 30.POWER ENTRY
C484  0.1uF  [C0402]
C487  0.1uF  [C0402]
C489  0.1uF  [C0402]
C490  1.0nF  [C0402]
C887  0.47UF  [EMIFIL_101X43W474MV4E]
C888  330uF  [25SVPF330M]
C889  330uF  [25SVPF330M]
C890  22uF  [C0805]
C891  22uF  [C0805]
C892  100uF  [C2917]
C893  22uF  [C0805]
D16  LED  [LED_LTST-C190]
D29  5.0SMDJ26CA  [DIOM7959X262N_LF_BI]
D30  5.0SMDJ26CA  [DIOM7959X262N_LF_BI]
D31  5.0SMDJ26CA  [DIOM7959X262N_LF_BI]
D34  LED  [LED_LTST-C190]
D35  LED  [LED_LTST-C190]
FB7  120E/DNP  [INDC1608X95M]
FB8  120E/DNP  [INDC1608X95M]
J30  DF33C-4DP-3.3DSA  [DF33C-4DP-330DSA]
R303  10K  [R0402]
R304  10E  [R0402]
R305  0.002  [R2512]
R306  10E  [R0402]
R307  10K  [R0402]
R308  10K  [R0402]
R309  620E  [R0805]
R310  1M/DNP  [R0402]
R311  150K  [R0402]
R312  150K  [R0402]
R845  1M  [R0402]
R846  1M  [R0402]
R847  1M  [R0402]
R848  75K  [R0402]
R849  41.2K  [R0402]
R850  41.2K  [R0402]
R851  1.1M  [R0402]
R852  10K  [R0402]
R886  620E  [R0805]
R887  620E  [R0805]
R909  0  [R0402]
U26  INA226  [VSSOP50P490X110-10N]
U27  TPS259241  [TPS259241]
U90  LTC4419IMSE  [MSOP12-065-0504LH]
sheet 33.3V3_T & 5V REG
C532  0.1uF  [C0402]
C533  10uF  [C0805]
C534  10uF  [C0805]
C535  1uF  [C0402]
C536  0.1uF  [C0402]
C537  0.1uF  [C0402]
C538  1uF  [C0402]
C539  10uF  [C0805]
C540  0.1uF  [R0402]
C541  10uF  [C0805]
C542  1uF  [C0402]
C543  0.1uF  [C0402]
C544  10pF  [R0402]
C545  22uF  [C0805]
C546  100uF  [C2917]
C547  22uF  [C0805]
C548  22uF  [C0805]
C549  22uF  [C0805]
C550  0.1uF  [C0402]
C551  0.1uF  [C0402]
C552  22uF  [C0805]
C553  330uF  [CT7343]
C554  330uF  [CT7343]
C555  560pF  [C0402]
C556  1uF  [C0402]
C557  0.1uF  [C0402]
C558  0.022uF  [C0402]
D36  LED  [LED_LTST-C190]
L31  2.2uH  [WURTH_744777910]
L32  1.0uH  [IND690690X400]
R352  10E  [R0402]
R353  10K  [R0402]
R354  100K  [R0402]
R355  0.002  [R2512]
R356  10E  [R0402]
R357  10K  [R0402]
R358  0  [R0402]
R359  10K  [R0402]
R360  100K  [R0402]
R361  10K  [R0402]
R362  0  [R0402]
R363  12K  [R0402]
R364  10K/DNP  [R0402]
R365  240K/1%  [R0402]
R366  41.2K/1%  [R0402]
R367  100K  [R0402]
R368  10K  [R0402]
R370  10K  [R0402]
R371  1.37K  [R0402]
R372  4.7K  [R0402]
R373  30K  [R0402]
R374  0  [R0402]
R870  0  [R1812]
R876  0  [R1812]
R888  200  [R0402]
TP33  TP_PWR  [TP_TH_40MIL]
TP34  TP_PWR  [TP_TH_40MIL]
TP74  TP_PWR  [TP_TH_40MIL]
TP75  TP_PWR  [TP_TH_40MIL]
U31  LT8640EUDC  [QFN50P300X400X80-20N]
U32  INA226  [VSSOP50P490X110-10N]
U33  MPQ8633A  [QFN21_MPQ8633A]

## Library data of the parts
C433 C434 C436 C437 C459 C460 C462 C463 C894-C901 = CAP_0: CAP CER 0.1UF 25V 10% X7R 0402; Manufacturer: MURATA; Manufacturer Part Number: GRM155R71C104KA88D; Part Number: 106G610423JD; Tolerance: +/-10%; Voltage: 25V
C902 = CAP_NONPOL: CAP CER 10UF 6.3V X5R 0603; MFG: MURATA; MFG_PN: GRM188R60J106KE47D; Manufacturer: MURATA; Manufacturer Part Number: GRM188R60J106KE47D; Tolerance: ±10%; Voltage: 6.3V
C907-C909 = cap_0402_0.01uF_16V_10%_X7R: CAP 0402 0.01uF 25V 10% X7R; Manufacturer: Murata; Manufacturer Part Number: GRM155R71E103KA01D; Voltage: 25V
D16 D32 D33 D36 D39 = LED_wp117: LED GREEN DIFFUSED 0603 SMD; Manufacturer: Lumex; Manufacturer Part Number: SML-LX0603GW-TR; Part Number: LTST-C190KGKT
FB25 FB26 = fer_120_1.5A_BLM15EG121SN1D_sm: Manufacturer: MURATA; Manufacturer Part Number: BLM15EG121SN1D
R856 R858 = RESISTOR_1: RES SMD 0.0OHM JUMPER 1/16W 0402; MFG: Panasonic; MFG_PN: ERJ-2GE0R00X; Manufacturer: VISHAY DALE; Manufacturer Part Number: CRCW04020000Z0ED; Wattage: 1/16W
R363 R857 = RES_0402: RES SMD 12K OHM 1% 1/16W 0402; Manufacturer: Yageo; Manufacturer Part Number: RC0402FR-0712KL
R860 R861 R863 R864 = RESISTOR_1: RES SMD 100K OHM 5% 1/16W 0402; Manufacturer: VISHAY DALE; Manufacturer Part Number: CRCW0402100KJNED; Tolerance: 5%; Wattage: 1/16W
R862 R865 R888 = RESISTOR_1: RES SMD 200 OHM 1% 1/16W 0402; Manufacturer: VISHAY DALE; Manufacturer Part Number: CRCW0402200RFKED; Tolerance: 1%; Wattage: 1/16W
R883 = res_0402_1K0_0.063W_1%_smd: RES SMD 1K OHM 5% 1/16W 0402; Manufacturer: VISHAY DALE; Manufacturer Part Number: CRCW04021K00JNED; Tolerance: ?%
R207-R218 R884 = RESISTOR_1: RES SMD 22 OHM 1% 1/16W 0402; MFG: VISHAY DALE; MFG_PN: CRCW040222R0FKED; Manufacturer: VISHAY DALE; Manufacturer Part Number: CRCW040222R0FKED; Tolerance: ±1%; Wattage: 1/16W
U91 = USB2514BI
X6 = CB3LV-3I-50M0000-T: OSC XO 24.000MHZ HCMOS SMD; MFG: Abracon; Manufacturer: ECS inc.
C379-C386 C418 C438-C440 C442 C443 C464-C466 C468 C469 C550 C551 C557 = CAP_NONPOL: CAP CER 0.1UF 25V 10% X7R 0402; Manufacturer: MURATA; Manufacturer Part Number: GRM155R71C104KA88D; Tolerance: ±10%; Voltage: 25V
C387 C388 = CAP: CAP CER 1000PF 3KV X7R 1812; Assembly Option: LOAD; Manufacturer: KEMET; Manufacturer PN: C1812C102KHRACTU; Manufacturer Part Number: C1812C102KHRACTU; PART_NUMBER: PAC_CAP_02425; Tolerance: 10%; Voltage: 3KV
R170-R177 = RES_0: RES SMD 75 OHM 1% 1/8W 0603; Assembly Option: LOAD; Manufacturer: Stackpole Electronics Inc.; Manufacturer PN: RNCP0603FTD75R0; Manufacturer Part Number: RNCP0603FTD75R0; PART_NUMBER: PAC_RES_01894; Tolerance: 1%
T3 T4 = MAGNETICS_H5007NL: MODULE SINGLE GIGABIT LAN 24SOIC; Manufacturer: Pulse Electronics Corporation
C412 C413 C415-C417 = cap_0402_0.1uF_16V_10%_X7R: CAP CER 0.1UF 25V 10% X7R 0402; MATERIAL: X7R; MFG: TAIYO; MFG_PN: TMK105BJ104KV-F; Manufacturer: MURATA; Manufacturer Part Number: GRM155R71C104KA88D; PART_NUMBER: G41157-001; PATH: I128; PHYS_PAGE: 25; Part Number: C1005X7R1E104K050BB; TOLERANCE: 10%; VOLTAGE: 25V; XY: (-4725,3525)
C419 = CAP_NONPOL: CAP-1.0UF,10%,10V,X5R,0402; Manufacturer: MURATA; Manufacturer Part Number: GRM155R61A105KE15D; Tolerance: ±10%; Voltage: 10V
C420 C421 C484 C487 C489 C532 C536 C537 = CAP_CER_0.1UF_10V_10%_X5R_0402: CAP CER 0.1UF 25V 10% X7R 0402; MATERIAL: X7R; Manufacturer: MURATA; Manufacturer Part Number: GRM155R71C104KA88D; PART_NUMBER: 0.1UF; Part Number: C1005X7R1E104K050BB; TOLERANCE: 10%; VOLTAGE: 25V
C422 = CAP_CER_0.1UF_10V_10%_X5R_0402: CAP CER 680PF 50V X7R 0402; MATERIAL: X7R; Manufacturer: Samsung Electro-Mechanics America, Inc; Manufacturer Part Number: CL05B681KB5NNNC; PART_NUMBER: 0.1UF; Part Number: CL05B681KB5NNNC; TOLERANCE: 10%; VOLTAGE: 50V
D8 D10 = DIODE_SCHOTTKY_30V_0.2A_SOD523: Manufacturer Part Number: PMEG3002AEB,115
D9 = DIODE_SCHOTTKY_30V_0.2A_SOD523: DIODE SCHOTTKY 30V 0.2A SOD523; Manufacturer Part Number: PMEG3002AEB,115; Part Number: PMEG3002AEB,115
J9 = eJTAG_Header_0: 8 Positions Header, Unshrouded Connector 0.050" (1.27mm) Surface Mount Gold; MANUFACTURER: Amphenol FCI
R206 R222 R223 R227 = R_1: RES SMD 1K OHM 5% 1/16W 0402; Manufacturer: VISHAY DALE; Manufacturer Part Number: CRCW04021K00JNED; Part Number: ERJ-2GEJ102X; TOLERANCE: 5%; WATTAGE: 1/10W
R219 R909 R947 = RES_1.0_OHM_1_16W_0402_SMD: RES SMD 0.0OHM JUMPER 1/16W 0402; MATERIAL: ?; Manufacturer: VISHAY DALE; Manufacturer Part Number: CRCW04020000Z0ED; Part Number: ERJ-2GE0R00X; TOLERANCE: ?; Wattage: 1/10W
R220 R224 R242 = R_1: RES 10K OHM 1/10W 5% 0402 SMD; Manufacturer: Panasonic Electronic Components; Part Number: ERJ-2GEJ103X; TOLERANCE: 5%; WATTAGE: 1/10W
R221 R246 = 100K-1_16W-5%-0603_0: RES 100K OHM 1/10W 5% 0402 SMD; Manufacturer: VISHAY DALE; Manufacturer Part Number: CRCW0402100KJNED; Part Number: ERJ-2GEJ104X; TOLERANCE: 5%; Wattage: 1/10W
R238 = 100K-1_16W-5%-0603_0: RES SMD 100K OHM 5% 1/16W 0402; Manufacturer: VISHAY DALE; Manufacturer Part Number: CRCW0402100KJNED; Part Number: ERJ-2GEJ104X; TOLERANCE: 5%; Wattage: 1/10W
R241 R243-R245 R247-R251 R267 R270-R272 R285 R288-R290 R852 = RESISTOR_1: RES SMD 10K OHM 5% 1/16W 0402; Manufacturer: VISHAY DALE; Manufacturer Part Number: CRCW040210K0JNED; Tolerance: ±5%; Wattage: 1/16W
TP12 = T_POINT1#1_1
U16 = TS3A27518ERTWR: IC MUX/DEMUX 6X1 24WQFN; Manufacturer: Texas Instruments
U18 = FPF1321: IC ADVANCED POWER SWITCH 6WLCSP; Manufacturer: Fairchild Semiconductor
U19 = N25Q128A: IC FLASH 128MBIT 108MHZ 8SO; Manufacturer: Winbond Electronics; Manufacturer Part Number: W25Q128JVSIQ-TR
U20 = TPS3808G50QDBVRQ1_1: IC VOLT SUPERVISOR ADJ SOT23-6; Manufacturer: TI; Part Number: TPS3808G18QDBVRQ1
C423-C426 C543 = CAP_0805: CAP CER 0.1UF 25V 10% X7R 0402; Manufacturer: MURATA; Manufacturer Part Number: GRM155R71C104KA88D; Voltage: 25V
C431 = CAP_NP: CAP CER 1000PF 3KV X7R 1812; Manufacturer: KEMET; Manufacturer Part Number: C1812C102KHRACTU; Part Number: GMC10CG102J50NT/NPO 5% 50V; Voltage: 3KV
CON1 = Mini-USB_CON_B: Manufacturer: Amphenol Commercial
R252-R255 R259-R261 = RES_0402: RES SMD 0.0OHM JUMPER 1/16W 0402; Manufacturer: VISHAY DALE; Manufacturer Part Number: CRCW04020000Z0ED
R256 R275 = RES: RES SMD 1K OHM 5% 1/16W 0402; Manufacturer: VISHAY DALE; Manufacturer Part Number: CRCW04021K00JNED; Part Number: 107B2115011D; Tolerance: ±5%; WATTAGE: 1/16W
R257 = RESN: RES 4.7K OHM 1/10W 5% 0402 SMD; Manufacturer: Panasonic; Manufacturer Part Number: ERJ-2GEJ472X; Part Number: ERJ-2GEJ472X; TOLERANCE: 5%; WATTAGE: 1/10W
R258 R364 = RES_0402
R265 = R: RES SMD 10M OHM 5% 1/16W 0402; Manufacturer: Vishay Dale; Manufacturer Part Number: CRCW040210M0JNED; Part Number: RK73H1JTTD1005F
R891 = RESISTOR_1: RES SMD 1K OHM 5% 1/16W 0402; MFG: VISHAY DALE; MFG_PN: CRCW04021K00JNED; Manufacturer: VISHAY DALE; Manufacturer Part Number: CRCW04021K00JNED; Tolerance: 1%; Wattage: 1/16W
U21 = SN74CB3Q3257PWR_1: IC QUAD1:2 FET MUX/DEMUX 16TSSOP; Manufacturer: TI
U22 = ADUM1201ARZ_0: DGTL ISO 2.5KV GEN PURP 8SOIC; Manufacturer: ANALOG DEVICES; Manufacturer Part Number: ADUM1201ARZ
U23 = FT230XQ_0: IC USB SERIAL BASIC UART 16QFN; Manufacturer: FTDI; Manufacturer Part Number: FT230XQ-R
C432 C435 C458 C461 = CAP_0: CAP CER 10UF 16V X5R 0805; Manufacturer: MURATA; Manufacturer Part Number: GRM21BR61C106KE15K; Part Number: 106G01062KJD; Tolerance: +/-10%; Voltage: 16V
C441 C467 = CAP_NONPOL: CAP CER 10UF 16V X5R 0805; Manufacturer: MURATA; Manufacturer Part Number: GRM21BR61C106KE15K; Tolerance: ±10%; Voltage: 16V
C449-C451 C470-C472 = CAP_NONPOL: CAP CER 0.1UF 25V 10% X7R 0402; Manufacturer: MURATA; Manufacturer Part Number: GRM155R71C104KA88D; Part Number: 106G61042J9D; Tolerance: ±10%; Voltage: 25V
C452 C473 = CAP_NONPOL: CAP CER 4.7UF 50V X5R 1206; Manufacturer: Taiyo Yuden; Manufacturer Part Number: UMK316BJ475KL-T; Part Number: 106G14755K7D; Tolerance: ±20%; Voltage: 50V
D11 D12 = LED: LED RED DIFFUSED 0603 SMD; Manufacturer: Lumex; Manufacturer Part Number: SML-LX0603IW-TR
J12 = CON-SM-PCIEXP-MINI-F: CONN 52POS MINI EXPRESS CARD SMD; Manufacturer: JAE Electronics
J13 J15 = Latch_PCIe_MINI_smd: Manufacturer: JAE
R268 R269 R286 R287 = RES: RES SMD 0.0OHM JUMPER 1/16W 0603; Manufacturer: VISHAY DALE; Manufacturer Part Number: CRCW06030000Z0EBC; Part Number: 107A210000ED; WATTAGE: 1/16W
R273 R292 = RES: RES SMD 0.0OHM JUMPER 1/16W 0402; Manufacturer: VISHAY DALE; Manufacturer Part Number: CRCW04020000Z0ED; Part Number: 107A210000ED; WATTAGE: 1/20W
R274 R293 = RES: RES SMD 10K OHM 5% 1/16W 0402; Manufacturer: VISHAY DALE; Manufacturer Part Number: CRCW040210K0JNED; Part Number: 107B2110021D; Tolerance: ±5%
R276 R294 = RES: RES SMD 200 OHM 1% 1/16W 0402; Manufacturer: VISHAY DALE; Manufacturer Part Number: CRCW0402200RFKED; Part Number: 107B2122001D; Tolerance: 1%
R277 R295 R859 = RES: RES SMD 0.0OHM JUMPER 1/16W 0402; Manufacturer: VISHAY DALE; Manufacturer Part Number: CRCW04020000Z0ED; Part Number: 107A210000ED; WATTAGE: 1/16W
R278 = RESISTOR_3: RES SMD 200 OHM 1% 1/16W 0402; Manufacturer: VISHAY DALE; Manufacturer Part Number: CRCW0402200RFKED; Part Number: 107B2130001D; Tolerance: 1%
TP17 TP24 = TEST_POINT
J14 = CON-SM-PCIEXP-MINI-F: CONN 52POS MINI EXPRESS CARD SMD; Manufacturer: JAE Electronics; Part Number: MM60-52B1-G1-R850
R291 = RES: RES SMD 1K OHM 5% 1/16W 0402; Manufacturer: VISHAY DALE; Manufacturer Part Number: CRCW04021K00JNED; Part Number: RC0402FR-071K5L; Tolerance: ±5%; WATTAGE: 1/16W
R300 = RESISTOR_3: RES SMD 200 OHM 1% 1/16W 0402; Manufacturer: VISHAY DALE; Manufacturer Part Number: CRCW0402200RFKED; Part Number: 107B2130001D; TOLERANCE: 1%
C490 = CAP_CER_0.1UF_10V_10%_X5R_0402: CAP CER 1.0nF 50V X7R 0402; MATERIAL: X7R; Manufacturer: KEMET; Manufacturer Part Number: C0402T102K5RACTU; PART_NUMBER: 0.1UF; Part Number: GRM155R72A102KA01D; TOLERANCE: 10%; VOLTAGE: 50V
C887 = CAP_CER_X2Y_0603_100pF_20%: CAP CER 0.47UF 100V X7R 1812; Manufacturer: Johanson Dielectrics Inc; Manufacturer Part Number: 101X43W474MV4E; Part Number: 101X43W474MV4E; Voltage: 100V
C888 C889 = CAP_POL_1: CAP ALUM POLY 330UF 20% 25V SMD; Manufacturer: Panasonic; Tolerance: 20%; Voltage: 25V
C545 C547-C549 C552 C890 C891 = CAP_NONPOL: CAP CER 22UF 25V X5R 0805; Manufacturer: MURATA; Manufacturer Part Number: GRM21BR61E226ME44L; Tolerance: ±20%; Voltage: 25V
C546 C892 = CAP_POL_1: CAP TANT 100UF 25V 10% 2917; Manufacturer: KEMET; Manufacturer Part Number: T491X107K025AT; Tolerance: ±10%; Voltage: 25V
C893 = CAP_NONPOL: CAP CER 22UF 25V X5R 0805; Manufacturer: MURATA; Manufacturer Part Number: GRM21BR61E226ME44L; Tolerance: 10%; Voltage: 25V
D29-D31 = SMDJ36CA: TVS DIODE 26VWM 42.1VC SMD; Manufacturer: Littelfuse Inc; Voltage: 26V
D34 D35 = LED_wp117: LED RED DIFFUSED 0603 SMD; Manufacturer: Lumex; Manufacturer Part Number: SML-LX0603IW-TR; Part Number: LTST-C190KRKT
FB7 FB8 = FB_1: FERRITE CHIP 120 OHM 2000MA 0603; Manufacturer: Murata Electronics North America; Manufacturer Part Number: BLM18PG121SN1D; Part Number: BLM18PG121SN1D
J30 = DF33C-4DP-3.3DSA
R303 R307 R308 R353 R359 R361 = RESISTOR_2: RES 10K OHM 1/10W 5% 0402 SMD; Manufacturer: Panasonic Electronic Components; Part Number: ERJ-2GEJ103X; TOLERANCE: 5%; WATTAGE: 1/10W
R304 R306 R352 R356 = RES_1.0_OHM_1_16W_0402_SMD: RES SMD 10 OHM 1% 1/10W 0402; MATERIAL: ?; Manufacturer: Panasonic Electronic Components; Part Number: ERJ-2RKF10R0X; TOLERANCE: 1%; Wattage: 1/10W
R305 R355 = RES_0.9_OHM_1_10W_1%_0402_SMD: RES SMD 0.002 OHM 1% 2W 2512; Manufacturer: Stackpole Electronics Inc; Manufacturer Part Number: CSNL2512FT2L00; Part Number: CSNL2512FT2L00; TOLERANCE: 1%; WATTAGE: 2W
R309 R886 R887 = RESISTOR_2: RES SMD 620 OHM 5% 0.4W 0805; Manufacturer: Rohm Semiconductor; Manufacturer Part Number: ESR10EZPJ621; Part Number: ESR10EZPJ621; TOLERANCE: 5%; WATTAGE: 0.4W
R310 R845-R847 = RESISTOR_2: RES SMD 1M OHM 1% 1/16W 0402; Manufacturer: VISHAY DALE; Manufacturer Part Number: CRCW04021M00FKED; Part Number: RC0402FR-071ML; TOLERANCE: 1%; WATTAGE: 1/16W
R311 = RESISTOR_2: RES SMD 150K OHM 1% 1/16W 0402; Manufacturer: Yageo; Manufacturer Part Number: RC0402FR-07150KL; Part Number: RC0402FR-07150KL; TOLERANCE: 1%; WATTAGE: 1/10W
R312 = RESISTOR_2: RES SMD 150K OHM 1% 1/16W 0402; Manufacturer: Yageo; Manufacturer Part Number: RC0402FR-07150KL; Part Number: RMCF0402FT1150K; TOLERANCE: 1%; WATTAGE: 1/16w
R848 = RESISTOR_2: RES SMD 75K OHM 1% 1/16W 0402; Manufacturer: VISHAY DALE; Manufacturer Part Number: CRCW040275K0FKED; Part Number: RC0402FR-071ML; TOLERANCE: 1%; WATTAGE: 1/16W
R849 R850 = RESISTOR_2: RES SMD 41.2k OHM 1% 1/16W 0402; Manufacturer: VISHAY DALE; Manufacturer Part Number: CRCW040241K2FKED; Part Number: RC0402FR-071ML; TOLERANCE: 1%; WATTAGE: 1/16W
R851 = RESISTOR_2: RES SMD 1.1M OHM 1% 1/16W 0402; Manufacturer: VISHAY DALE; Manufacturer Part Number: CRCW04021M10FKED; Part Number: RC0402FR-071ML; TOLERANCE: 1%; WATTAGE: 1/16W
U26 U32 = INA226_6: IC MONITOR PWR/CURR BIDIR 10MSOP; Manufacturer: Texas Instruments; Manufacturer Part Number: INA226AIDGSR; Part Number: INA226AIDGSR
U27 = TPS259241: IC EFUSE 12V BFET DVR 5A 10VSON; Manufacturer: Texas Instruments; Manufacturer Part Number: TPS259241DRCR; Part Number: TPS259241DRCR
U90 = LTC4419IMSE_0: IC SOURCE SELECTOR SWITCH 12MSOP
C533 C534 C539 = CAP_0805
C535 C538 C542 C556 = CAP_NONPOL: CAP CER 1UF 25V 10% X5R 0402; Manufacturer: MURATA; Manufacturer Part Number: GRM155R61E105KA12J; Tolerance: ±10%; Voltage: 25V
C540 = CAP_NP: CAP CER 0.1UF 25V 10% X7R 0402; Manufacturer: MURATA; Manufacturer Part Number: GRM155R71C104KA88D; Voltage: 25V
C541 = CAP_NP: CAP,Y5V,+80-20%,SMD0805,16V; MDS PN: 06-Y1040501
C544 = CAP_NP: CAP,X7R,10%,SMD0603,50V; Manufacturer: Fenghua Advanced Technology
C553 C554 = CAP_POL_1: CAP TANT POLY 330UF 6.3V 2917; Manufacturer: Panasonic; Manufacturer Part Number: 6TPF330M9L; Tolerance: ±20%; Voltage: 6.3V
C555 = CAP_NONPOL: CAP CER 560PF 50V X7R 0402; Manufacturer: MURATA; Manufacturer Part Number: GRM155R71H561KA01D; Tolerance: ±10%; Voltage: 50V
C558 = CAP_NONPOL: CAP CER 0.022UF 50V X5R 0402; Manufacturer: TDK Corporation; Manufacturer Part Number: CGA2B3X5R1H223K050BB; Tolerance: ±10%; Voltage: 50V
L31 = INDUCTOR_2.8uH: FIXED IND 2.2UH 4.2A 20 MOHM SMD; MATERIAL: ?; Manufacturer: Wurth Electronics Inc; Manufacturer Part Number: 7447779002; Part Number: 7447779002
L32 = INDUCTOR_0: FIXED IND 1UH 15A 4.6 MOHM SMD; Manufacturer: WURTH; Manufacturer Part Number: 744311100
R354 R360 = RES_0402: Manufacturer: VISHAY DALE; Manufacturer Part Number: CRCW0402100KJNED
R357 = RES_0402: RES SMD 10K OHM 5% 1/16W 0402
R358 = R_0: RES 150 OHM 1/10W 5% 0603 SMD; Manufacturer: VISHAY DALE; Manufacturer Part Number: CRCW04020000Z0ED; Power: 1/10W; Tolerance: 5%
R362 = R_0: RES SMD 0.0OHM JUMPER 1/16W 0402; Manufacturer: VISHAY DALE; Manufacturer Part Number: CRCW04020000Z0ED; Power: 1/10W; Tolerance: 5%
R365 = R_0: RES SMD 240K OHM 1% 1/16W 0402; Manufacturer: VISHAY DALE; Manufacturer Part Number: CRCW0402240KFKED; Power: 1/10W; Tolerance: 1%
R366 = RES_0402: RES SMD 41.2K OHM 1% 1/16W 0402; Manufacturer: Yageo; Manufacturer Part Number: RC0402FR-0741K2L
R367 = RES_0402: RES SMD 100K OHM 1% 1/16W 0402; Manufacturer: VISHAY DALE; Manufacturer Part Number: CRCW0402100KFKED; Tolerance: 1%
R368 R370 = RESISTOR_1: RES SMD 10K OHM 1% 1/16W 0402; Manufacturer: VISHAY DALE; Manufacturer Part Number: CRCW040210K0FKED; Tolerance: 1%; Wattage: 1/16W
R371 = RESISTOR_1: RES SMD 1.37K OHM 1% 1/10W 0402; Manufacturer: Panasonic; Manufacturer Part Number: ERJ-2RKF1371X; Tolerance: 1%; Wattage: 1/16W
R372 = RESISTOR_1: RES SMD 4.87K OHM 1% 1/16W 0402; Manufacturer: Panasonic; Manufacturer Part Number: ERJ-2GEJ472X; Tolerance: ±1%; Wattage: 1/16W
R373 = RESISTOR_1: RES SMD 30.1K OHM 1% 1/16W 0402; Manufacturer: VISHAY DALE; Manufacturer Part Number: CRCW040230K1FKED; Tolerance: ±1%; Wattage: 1/16W
R374 = RES_0: RES SMD 0.0OHM JUMPER 1/16W 0402; Assembly Option: LOAD; Manufacturer: VISHAY DALE; Manufacturer PN: ERJ-2RKF1002X; Manufacturer Part Number: CRCW04020000Z0ED; PART_NUMBER: PAC_RES_02050
R870 R876 = R: RES SMD 0 OHM 1W 1812 WIDE; Manufacturer: Vishay Dale; Manufacturer Part Number: RCL12180000Z0EK
TP33 TP34 TP74 TP75 = T_POINT_R
U31 = LT8610EMSE-EMSE16_0: IC REG BUCK ADJ 5A 20QFN; Manufacturer: Linear Technology; Part Number: LT8640EUDC#PBF
U33 = MPQ8633A: Manufacturer: MPS; Manufacturer Part Number: MPQ8633AGLE-Z

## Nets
AGND1: C556.2 C558.2 R372.1 R373.1 R374.2 U33.2(AGND)
GND: C379.2 C380.1 C381.2 C382.1 C383.2 C384.1 C385.2 C386.1 C387.1 C388.1 C412.2 C413.2 C415.2 C416.2 C417.2 C418.2 C419.2 C420.2(B[0]) C421.2(B[0]) C422.2(B[0]) C423.1 C424.1 C425.1 C426.1 C431.1 C432.2 C433.2 C434.2 C435.2 C436.2 C437.2 C438.2 C439.2 C440.2 C441.2 C449.2 C450.2 C451.2 C452.2 C458.2 C459.2 C460.2 C461.2 C462.2 C463.2 C464.2 C465.2 C466.2 C467.2 C470.2 C471.2 C472.2 C473.2 C484.1(A[0]) C489.2(B[0]) C490.2(B[0]) C532.1(A[0]) C533.2 C534.2 C535.2 C538.2 C539.2 C540.2 C541.2 C542.2 C543.2 C545.2 C546.2N C547.2 C548.2 C549.2 C550.2 C552.2 C553.2N C554.2N C557.2 C887.2(B) C888.2N C889.2N C890.2 C891.2 C892.2N C893.2 C894.1 C895.2 C896.1 C897.1 C898.1 C899.1 C900.1 C901.1 C902.2 C907.1 C908.2 C909.1 CON1.5(GND) D16.K D31.2 D32.K D33.K D34.K D35.K D36.K D39.K J9.7 J12.4(GND) J12.9(GND) J12.15(GND) J12.18(GND) J12.21(GND) J12.26(GND) J12.27(GND) J12.29(GND) J12.34(GND) J12.35(GND) J12.40(GND) J12.50(GND) J12.53(GND) J12.54(GND) J13.1 J13.2 J13.3 J13.4 J13.5 J13.6 J14.4(GND) J14.9(GND) J14.15(GND) J14.18(GND) J14.21(GND) J14.26(GND) J14.27(GND) J14.29(GND) J14.34(GND) J14.35(GND) J14.40(GND) J14.50(GND) J14.53(GND) J14.54(GND) J15.1 J15.2 J15.3 J15.4 J15.5 J15.6 J30.3 J30.4 R220.2(B[0]) R221.1(A[0]) R238.1(A[0]) R246.1(A[0]) R256.1(Pin1) R257.2(B[0]) R265.2 R308.2 R311.1 R312.1 R359.1 R361.1 R363.2 R364.2 R366.2 R367.2 R371.1 R374.1 R849.2 R850.2 R857.2 R860.1 R861.1 R863.1 R864.1 TP34.1(TP) TP75.1(TP) U16.2(GND) U16.25(PAD) U18.C1(GND) U19.4(GND) U20.2(GND) U21.8(GND) U22.4(GND1) U22.5(GND2) U23.3(GND1) U23.13(GND2) U23.17(PAD) U26.7(GND) U27.11(PAD) U31.6(GND1) U31.7(GND2) U31.10(GND3) U31.11(GND4) U31.18(GND) U32.7(GND) U33.6(RGND) U33.11(PGND1) U33.12(PGND2) U33.13(PGND3) U33.14(PGND4) U33.15(PGND5) U33.16(PGND6) U33.17(PGND7) U33.18(PGND8) U90.5(GND) U90.13(EGND) U91.37(GROUND) X6.2(GND) ; also on sheet 1 2 10 11 12 13 14 15 16 17 18 19 20 21 30 31 32 33 34 35 36 37 38 39 40 41 42 43 44 45 46 47 48 49 50 51 52 53 54
V1P5: C438.1 C439.1 C440.1 C441.1 C464.1 C465.1 C466.1 C467.1 R269.2(Pin2) R287.2(Pin2) ; also on sheet 14 31 51
V2_BACK_ON: R852.1 U90.8(V2ON) ; also on sheet 37
V3P3: C416.1 C424.2 C449.1 C450.1 C451.1 C452.1 C470.1 C471.1 C472.1 C473.1 C896.2 C897.2 C902.1 FB25.2 FB26.2 R206.1(A[0]) R222.1(A[0]) R223.1(A[0]) R224.1(A[0]) R247.2 R248.2 R249.2 R250.2 R251.2 R267.2 R268.2(Pin2) R270.2 R271.2 R272.2 R274.2(Pin2) R275.2(Pin2) R278.2 R285.2 R286.2(Pin2) R288.2 R289.2 R290.2 R291.2(Pin2) R293.2(Pin2) R300.2 R368.2 R856.2 U18.C2(VINB) U21.16(VCC) U22.1(VDD1) U91.15(VDD33_1) U91.23(VDD33_2) ; also on sheet 10 11 12 14 17 18 30 31 32 33 34 35 43 45 49 51 53 54
V3P3_SPI_CONN: C413.1 C415.1 J9.2 R227.1(A[0]) R244.2 U18.A2(VINA)
V3P3_TIVA_CM_PG: R360.2 U31.19(PG)
V3P3_TIVA_FB: C544.1 R365.2 R367.1 U31.20(FB)
V3P3_TIVA_LT: C484.2(B[0]) C532.2(B[0]) R303.2 R307.1 R353.2 R852.2 R876.2 R888.2 TP74.1(TP) U26.6(VS) U32.6(VS) ; also on sheet 1 2 19 20 21 31 37 38 39 40 42 43 44 46 47 52 54
V3P3_TIVA_LTOUT: C539.1 C540.1 C541.1 C544.2 L31.2(INB) R360.1 R362.1 R365.1 R876.1
V5P0: C552.1 C553.1P C554.1P C555.1 L32.2 R258.2 R370.2 TP33.1(TP) ; also on sheet 18 30 31 33 38 49
V5P0_PG: U33.9(PGOOD) ; also on sheet 33
V12P0: C890.1 J30.2 R304.2(B[0]) R305.1(A[0]) R847.1 R886.2 U90.1(V1) ; also on sheet 18 21 31
V12P0_BACK_TIVA: C887.1(A) C888.1P C889.1P C891.1 D30.1 J30.1 R851.1 R887.2 U90.12(V2)
V12P0_OCT_5V: C545.1 C546.1P C547.1 C548.1 C549.1 C550.1 R870.2 U33.10(VIN1) U33.21(VIN2)
V12P0_OCT_CM: C489.1(A[0]) FB7.2 FB8.2 R305.2(B[0]) R306.2(B[0]) R310.2 U26.8(VBUS) U27.3(VIN) U27.4(VIN1) U27.5(VIN2)
V12P0_OCT_R: FB7.1 FB8.1 R309.2 R870.1 U27.6(OUT) U27.7(OUT1) U27.8(OUT2) ; also on sheet 30 54
V12P0_TIVA: C533.1 C534.1 C535.1 C538.1 R354.1 R355.2(B[0]) R356.2(B[0]) U31.4(VIN1) U31.13(VIN2) U32.8(VBUS) ; also on sheet 39
V12P0_TIVA_CM: C892.1P C893.1 R352.2(B[0]) R355.1(A[0]) R845.1 R846.1 U90.9(OUT)
VDD_OSC_USB: C907.2 FB26.1 R883.2 X6.4(VCC)
VDDA_3V3_HUB: C898.2 C899.2 C900.2 C901.2 FB25.1 U91.5(VDDA33_1) U91.10(VDDA33_2) U91.29(VDDA33_3) U91.36(VDDA33_4)
BB_ETH_MDI_N0: T4.3(TD1-) ; also on sheet 42
BB_ETH_MDI_N1: T4.6(TD2-) ; also on sheet 42
BB_ETH_MDI_N2: T4.9(TD3-) ; also on sheet 42
BB_ETH_MDI_N3: T4.12(TD4-) ; also on sheet 42
BB_ETH_MDI_P0: T4.2(TD1+) ; also on sheet 42
BB_ETH_MDI_P1: T4.5(TD2+) ; also on sheet 42
BB_ETH_MDI_P2: T4.8(TD3+) ; also on sheet 42
BB_ETH_MDI_P3: T4.11(TD4+) ; also on sheet 42
CFG_SEL0: R860.2 U91.24(SCLK/CFG_SEL0)
CFG_SEL1: R861.2 R862.2 U91.25(HS_IND/CFG_SEL1)
CHASIS_GND: C431.2 C887.3(G) CON1.6(CGND1) CON1.7(CGND2) D29.2 R265.1 ; also on sheet 2 21
DLM2_RX0_N: C442.1 ; also on sheet 50
DLM2_RX0_P: C443.1 ; also on sheet 50
DLM2_RX1_N: C468.1 ; also on sheet 50
DLM2_RX1_P: C469.1 ; also on sheet 50
DLM2_TX0_N: J12.31(PETn0) ; also on sheet 50
DLM2_TX0_P: J12.33(PETp0) ; also on sheet 50
DLM2_TX1_N: J14.31(PETn0) ; also on sheet 50
DLM2_TX1_P: J14.33(PETp0) ; also on sheet 50
ISO0_5V: C423.2 C425.2 R258.1 R259.1 R891.1 U22.8(VDD2) U23.10(VCC)
ISO_OCT_UART0_RXD: R260.1 U21.5(2B1)
ISO_OCT_UART0_TXD: R261.1 U21.2(1B1)
LT8640_INT_VCC: C542.1 R357.1 U31.2(INTVCC)
MEM_RESET_L: R858.2 ; also on sheet 32 43 44 45 49
MINI_PCIE0_100MHZ_N: J12.11(REFCLK-) ; also on sheet 35
MINI_PCIE0_100MHZ_P: J12.13(REFCLK+) ; also on sheet 35
MINI_PCIE1_100MHZ_N: J14.11(REFCLK-) ; also on sheet 35
MINI_PCIE1_100MHZ_P: J14.13(REFCLK+) ; also on sheet 35
MPCIE0_LED_WLAN#: D11.C R272.1 R273.1(Pin1)
mPCIE0_USB_DM: J12.36(USB_D-) U91.1(USB_DM_DN1/PRT_DIS_M1)
mPCIE0_USB_DP: J12.38(USB_D+) U91.2(USB_DP_DN1/PRT_DIS_P1)
MPCIE0_WAKE#: R267.1 R276.1(Pin1) ; also on sheet 10
MPCIE1_LED_WLAN#: D12.C R290.1 R292.1(Pin1)
mPCIE1_RST_L: R859.1(Pin1) ; also on sheet 10
mPCIE1_USB_DM: J14.36(USB_D-) U91.3(USB_DM_DN2/PRT_DIS_M2)
mPCIE1_USB_DP: J14.38(USB_D+) U91.4(USB_DP_DN2/PRT_DIS_P2)
MPCIE1_WAKE#: R285.1 R294.1(Pin1) ; also on sheet 10
NON_REM0: R864.2 R865.2 U91.28(SUSP_IND/LOCAL_PWR/NON_REM0)
NON_REM1: R863.2 U91.22(SDA/NO_REMI1)
OCT_12V_ONOFF: R909.1(A[0]) ; also on sheet 37
OCT_PWR_ALRT: R303.1 U26.3(ALERT) ; also on sheet 37
OCT_SPI_CLK: R208.2 ; also on sheet 53
OCT_SPI_CS0_L: R212.2 ; also on sheet 53
OCT_SPI_MISO: R210.2 ; also on sheet 53
OCT_SPI_MOSI: R209.2 ; also on sheet 53
OCT_TWS1_SCL: J12.30(SMB_CLK) J14.30(SMB_CLK) R271.1 R289.1 ; also on sheet 11 18 48 52 53
OCT_TWS1_SDA: J12.32(SMB_DATA) J14.32(SMB_DATA) R270.1 R288.1 ; also on sheet 11 18 48 52 53
OCT_UART0_RXD: R248.1 R253.1 ; also on sheet 53
OCT_UART0_TXD: R247.1 R252.1 ; also on sheet 53
OCT_UART0_USBDM: CON1.2(D-) U23.7(USBDM)
OCT_UART0_USBDP: CON1.3(D+) U23.6(USBDP)
OCT_USB0_DM: U91.30(USBDM_UP) ; also on sheet 53
OCT_USB0_DP: U91.31(USBDP_UP) ; also on sheet 53
OCT_USB0_RXD: U22.6(VOB) U23.2(RXD)
OCT_USB0_TXD: U22.7(VIA) U23.15(TXD)
P2_TRCT1: C379.1 T3.1(TCT1)
P2_TRCT2: C381.1 T3.4(TCT2)
P2_TRCT3: C383.1 T3.7(TCT3)
P2_TRCT4: C385.1 T3.10(TCT4)
P3_ETHSW_D0N: T3.3(TD1-) ; also on sheet 19
P3_ETHSW_D0P: T3.2(TD1+) ; also on sheet 19
P3_ETHSW_D1N: T3.6(TD2-) ; also on sheet 19
P3_ETHSW_D1P: T3.5(TD2+) ; also on sheet 19
P3_ETHSW_D2N: T3.9(TD3-) ; also on sheet 19
P3_ETHSW_D2P: T3.8(TD3+) ; also on sheet 19
P3_ETHSW_D3N: T3.12(TD4-) ; also on sheet 19
P3_ETHSW_D3P: T3.11(TD4+) ; also on sheet 19
P_SPI_CLK: R215.1 U16.23(NC1)
P_SPI_CS0_N: R218.1 U16.18(NC4)
P_SPI_MISO: R217.1 U16.20(NC3)
P_SPI_MOSI: R216.1 U16.22(NC2)
PERST1_L: R277.1(Pin1) R295.1(Pin1) ; also on sheet 50
PRGMR_HOLD_N: J9.4
PRGMR_IO3: J9.5 R219.2(B[0])
PRGMR_SPI_CLK: J9.6 R215.2
PRGMR_SPI_CS0_N: J9.1 R218.2
PRGMR_SPI_MISO: J9.3 R217.2
PRGMR_SPI_MOSI: J9.8 R216.2
SOC_FLASH_CLK: R207.1 U19.6(SCK)
SOC_FLASH_CS0_N: R214.1 R241.2 U19.1(~{CS})
SOC_FLASH_MISO: R213.1 R243.1 U19.2(SO)
SOC_FLASH_MOSI: R211.1 U19.5(SI)
SOC_FLASH_WP_N: R244.1 R246.2(B[0]) R947.2(B[0]) U19.3(~{WP})
SOC_FLASH_WP_N_R: R947.1(A[0]) U20.1(NRESET)
SPI0_CLK: R208.1 U16.8(NO1)
SPI0_CS0_N: R212.1 U16.14(NO4)
SPI0_MISO: R210.1 U16.12(NO3)
SPI0_MOSI: R209.1 U16.10(NO2)
SPI_FLASH_SW: D8.K D9.A R219.1(A[0]) R221.2(B[0]) U16.11(IN2) U16.21(IN1)
SPI_HOLD_L: R245.1 U19.7(~{HOLD})
SPI_PROG_SEL: D9.K R222.2(B[0]) ; also on sheet 10
SPI_PWR_EN: D10.K R227.2(B[0]) U18.A1(EN)
SPI_PWR_SEL: R224.2(B[0]) R238.2(B[0]) U18.B1(SEL)
SPI_SW_PWR: C412.1 C417.1 C418.1 C419.1 C420.1(A[0]) C421.1(A[0]) R241.1 R242.1(A[0]) R243.2 R245.2 U16.5(VCC) U18.B2(VOUT) U19.8(VCC) U20.5(SENSE) U20.6(VDD)
TIVA_OCT_UART3_RX: U21.3(1B2) ; also on sheet 37
TIVA_OCT_UART3_TX: U21.6(2B2) ; also on sheet 37
TIVA_PWR_ALRT: R353.1 U32.3(ALERT) ; also on sheet 37 38
TIVA_PWRMNTR_I2C6_SCLK: U26.5(SCL) U32.5(SCL) ; also on sheet 1 31 37 38 43
TIVA_PWRMNTR_I2C6_SDA: U26.4(SDA) U32.4(SDA) ; also on sheet 1 31 37 38 43
TIVA_USB0_5V: CON1.1(VBUS) R259.2
TIVA_USB0_DM: U91.6(USB_DM_DN3/PRT_DIS_M3) ; also on sheet 37
TIVA_USB0_DP: U91.7(USB_DP_DN3/PRT_DIS_P3) ; also on sheet 37
UART_SEL: R251.1 R256.2(Pin2) U21.1(S) ; also on sheet 10 37
USB_24MHZ: R884.1 U91.33(XTAL_IN/CLK_IN)
N22537488: C432.1 C433.1 C434.1 J12.2(3.3V) J12.24(3.3VAUX) J12.52(3.3V) R268.1(Pin1)
N22537589: J12.22(PERST_L) R275.1(Pin1) R277.2(Pin2)
N22537717: J12.1(WAKE_L) R274.1(Pin1) R276.2(Pin2)
N22537783: J12.44(LED_WLAN_L) R273.2(Pin2)
N22538260: D11.A R278.1
N22540659: J12.7(CLKREQ_L) TP17.1
N22542244: C442.2 J12.23(PERn0)
N22542251: C443.2 J12.25(PERp0)
N22542539: D12.A R300.1
N22543327: C435.1 C436.1 C437.1 J12.6(1.5V) J12.28(1.5V) J12.48(1.5V) R269.1(Pin1)
N22552284: C458.1 C459.1 C460.1 J14.2(3.3V) J14.24(3.3VAUX) J14.52(3.3V) R286.1(Pin1)
N22552383: J14.22(PERST_L) R291.1(Pin1) R295.2(Pin2) R859.2(Pin2)
N22552489: J14.1(WAKE_L) R293.1(Pin1) R294.2(Pin2)
N22552555: J14.44(LED_WLAN_L) R292.2(Pin2)
N22552886: J14.7(CLKREQ_L) TP24.1
N22552908: C468.2 J14.23(PERn0)
N22552910: C469.2 J14.25(PERp0)
N22552936: C461.1 C462.1 C463.1 J14.6(1.5V) J14.28(1.5V) J14.48(1.5V) R287.1(Pin1)
N30118778: C536.2(B[0]) L31.1(INA) U31.8(SW) U31.9(SW1) U31.21(SW2) U31.22(SW3)
N30118914: R358.1 U31.17(SYNC)
N30118916: R357.2 R358.2 R364.1
N30118992: C536.1(A[0]) U31.3(BST)
N30119008: R366.1 U31.15(RT)
N30119010: C543.1 U31.16(TR/SS)
N30119024: R354.2 R363.1 U31.14(EN/UV)
N30158858: C557.1 C558.1 U33.5(TRK_REF)
N30159030: C556.1 U33.19(VCC)
N30159078: R373.2 U33.4(MODE)
N30159092: R372.2 U33.3(CS)
N30159100: C551.2 U33.1(BST)
N30159104: C551.1 L32.1 U33.20(SW)
N30159176: C555.2 R370.1 R371.2 U33.7(FB)
N30267307: T3.23(MX1+) T4.23(MX1+)
N30267309: T3.22(MX1-) T4.22(MX1-)
N30267310: T3.20(MX2+) T4.20(MX2+)
N30267312: T3.19(MX2-) T4.19(MX2-)
N30267313: T3.17(MX3+) T4.17(MX3+)
N30267315: T3.16(MX3-) T4.16(MX3-)
N30267316: T3.14(MX4+) T4.14(MX4+)
N30267318: T3.13(MX4-) T4.13(MX4-)
N30267860: C387.2 R170.1 R172.1 R174.1 R176.1
N30268186: C388.2 R171.2 R173.2 R175.2 R177.2
N30268526: C380.2 T4.1(TCT1)
N30268527: C384.2 T4.7(TCT3)
N30268528: C382.2 T4.4(TCT2)
N30268529: C386.2 T4.10(TCT4)
N30694438: C426.2 U23.1(VCCIO) U23.8(3V3OUT) U23.9(RESET#)
N31031706: D8.A R206.2(B[0])
N31031738: R220.1(A[0]) TP12.1(A) U16.17(NEN)
N31031868: R207.2 U16.1(COM1)
N31031870: R211.2 U16.3(COM2)
N31031872: R213.2 U16.4(COM3)
N31031874: R214.2 U16.6(COM4)
N31033087: D10.A R223.2(B[0])
N31033468: R242.2(B[0]) U20.3(NMR)
N31033564: C422.1(A[0]) U20.4(CT)
N31236706: R257.1(A[0]) U21.15(OE)
N31237119: R250.1 R255.1
N31237123: R249.1 R254.1
N31238453: R255.2 U21.12(4A)
N31238455: R252.2 U21.4(1A)
N31238457: R254.2 U21.9(3A)
N31238459: R253.2 U21.7(2A)
N31650006: C487.1(A[0]) R304.1(A[0]) U26.10(IN+)
N31650008: C487.2(B[0]) R306.1(A[0]) U26.9(IN-)
N31650033: R308.1 U26.2(A0)
N31650035: R307.2 U26.1(A1)
N31653900: C537.1(A[0]) R352.1(A[0]) U32.10(IN+)
N31653902: C537.2(B[0]) R356.1(A[0]) U32.9(IN-)
N31653929: R359.2 U32.2(A0)
N31653931: R361.2 U32.1(A1)
N31655880: R362.2 U31.1(BIAS)
N31658835: R261.2 U22.3(VIB)
N31658837: R260.2 U22.2(VOA)
N32038605: D16.A R309.1
N32038678: R312.2 U27.10(ILIM)
N32038686: C490.1(A[0]) U27.1(DV/DT)
N32038708: R310.1 R311.2 R909.2(B[0]) U27.2(EN/UVLO)
N32330264: R368.1 U33.8(EN)
N33136918: D29.1 D30.2 D31.1
N33138409: R845.2 U90.6(CMPOUT1)
N33138421: R846.2 U90.7(CMPOUT2)
N33139203: R847.2 R848.1 U90.4(ADJ)
N33139213: R848.2 R849.1 U90.3(CMP1)
N33139987: R850.1 R851.2 U90.10(CMP2)
N33174267: R856.1 U91.27(VBUS_DET)
N33174298: R857.1 U91.35(RBIAS)
N33174384: R858.1 U91.26(RESET_N)
N33175078: C894.2 C908.1 U91.34(PLLFILT)
N33175180: C895.1 C909.2 U91.14(CRFILT)
N33224841: R884.2 X6.3(OUT)
N33224848: R883.1 X6.1(EN)
N33529458: D34.A R886.1
N33529732: D35.A R887.1
N33532473: D39.A R891.2
N34192279: D36.A R888.1
N34194538: R172.2 T3.21(MCT2)
N34194539: R176.2 T3.15(MCT4)
N34194540: R174.2 T3.18(MCT3)
N34194541: R170.2 T3.24(MCT1)
N34194542: R173.1 T4.21(MCT2)
N34194543: R171.1 T4.24(MCT1)
N34194544: R175.1 T4.18(MCT3)
N34194545: R177.1 T4.15(MCT4)
N34194704: D33.A R865.1
N34194705: D32.A R862.1

Not connected (* = marked no-connect by the designer): CON1 4(PIN_ID)*; J12 3(RESERVED1)* 5(RESERVED2)* 8(RESERVED3)* 10(RESERVED4)* 12(RESERVED5)* 14(RESERVED6)* 16(RESERVED7)* 17(RESERVED8)* 19(RESERVED9)* 20(RESERVED10)* 37(RESERVED11)* 39(RESERVED12)* 41(RESERVED13)* 42(LED_WWAN_L)* 43(RESERVED14)* 45(RESERVED15)* 46(LED_WPAN_L)* 47(RESERVED16)* 49(RESERVED17)* 51(RESERVED18)*; J14 3(RESERVED1) 5(RESERVED2) 8(RESERVED3)* 10(RESERVED4)* 12(RESERVED5) 14(RESERVED6) 16(RESERVED7) 17(RESERVED8) 19(RESERVED9) 20(RESERVED10) 37(RESERVED11)* 39(RESERVED12) 41(RESERVED13) 42(LED_WWAN_L)* 43(RESERVED14) 45(RESERVED15) 46(LED_WPAN_L)* 47(RESERVED16) 49(RESERVED17) 51(RESERVED18); U16 7(COM5)* 9(COM6)* 13(NO6)* 15(NO5)* 16(NC5)* 19(NC6)* 24(NC)*; U21 10(3B2)* 11(3B1)* 13(4B2)* 14(4B1)*; U23 4(CTS#) 5(CBUS2)* 11(CBUS1)* 12(CBUS0)* 14(CBUS3)* 16(RTS#); U27 9(BFET)*; U90 2(NC1)* 11(NC2)*; U91 8(USB_DM_DN4/PRT_DIS_M4)* 9(USB_DP_DN4/PRT_DIS_P4)* 11(TEST)* 12(PWRPRT1/BC_EN1)* 13(OCS_N1)* 16(PWRPRT2/BC_EN2)* 17(OCS_N2)* 18(PWRPRT3/BC_EN3)* 19(OCS_N3)* 20(PRTPWR4/BC_EN4)* 21(OCS_N4)* 32(XTAL_OUT)*

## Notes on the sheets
sheet 22
- IPU
- use default configuration
sheet 23
- connect to port3
- CONNECT TO GBC CONNECTOR
sheet 24
- To 81xx GPIO
- IN1,IN2=1: COMn=NOn
  IN1,IN2=0: COMn=NCn
- the default state should be 1
- SPI BOOT FLASH
- POWER SELECTION LOGIC
- SEL:0,VOUT=VINA
  SEL:1, VOUT=VINB
- DEDIPROG HEADER
- SPI 3V3 Monitor
sheet 25
- USB
- OCT_UAT0
- FT230
- OCT
- MUX
- TIVA_UART3
- TIVA
- Uart_SEL
- reference  Cavium_GBC-2_Detailed_Ver0.4.pptx
- to tiva gpio
- TIVA UART3  Connect to OCT UART0
- UART SEL
- LOW
- A TO B1
- HIGH
- A TO B2
sheet 26
- WLAN1 LED
- MINI_PCIE_SOCKET
- LATCH_MM60-JAE
- This page is for reference only and NOT for AS IS use.
  Users of this page of the schematics need to confirm
  the validity of similar circuitry in the user's application.
sheet 27
- to OCT gpio4
- WLAN2 LED
sheet 28
- UNLESS OTHERWISE SPECIFIED:
  RESISTORS ARE 0402 PACKAGE, POWER RATING < 0.5W & TOLERANCE > 1%
  CAPACITORS ARE 0402 PACKAGE & TOLERANCE OF 10%
- From power board
- 12V OCT power monitor
- Adress:0X44
- voperation 4.5~13.8
- Ilim, 5A
- U90 pcb layout recommend
- Vsw1=10.06V
- Vv1uv=10.5V
- Place R867,R868 after U27
- Vv2uv=10.7V
sheet 29
- use large copper shape
- R1218 JUMPER
- 4.2A
- ADDRESS 0X40
- VOUT=0.97V*(1+R1/R2)
- 12V TIVA power monitor
- (1MHz)
- use large copper shape
- Need to Confirm the Values
- Layout Note : This sense traces should be as short as possible
- use large copper shape
- RC0402FR-071K37L
- VOUT=0.6*/(1+R1/R2)
- R1218 JUMPER
